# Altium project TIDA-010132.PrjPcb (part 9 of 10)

## Sheet AFE2-LMX2594.SchDoc
size 558 x 431 mm; Date: Not shown in title block; ApprovedBy: Not shown in title block; CheckedBy: Not shown in title block; Author: Not shown in title block; CompanyName: Not shown in title block; DrawnBy: Avinash N; Engineer: Not shown in title block; Organization: Not shown in title block; Address1: Not shown in title block; Address2: Not shown in title block; Address3: Not shown in title block; Address4: Not shown in title block; DocumentNumber: 1; Revision: Use project parameter SCH_Rev; SheetNumber: 15; SheetTotal: 32; PageSetup: Record=PageOptions¦CenterHorizontal=True¦CenterVertical=True¦PrintScale=1.00¦XCorrection=1.00¦YCorrection=1.00¦PrintKind=0¦BorderSize=5000000¦LeftOffset=0¦BottomOffset=0¦Orientation=2¦PaperLength=1000¦PaperWidth=1000¦Scale=100¦PaperSource=15¦PrintQuality=600¦MediaType=1¦DitherType=10¦PaperKind=Letter¦PrintScaleMode=1
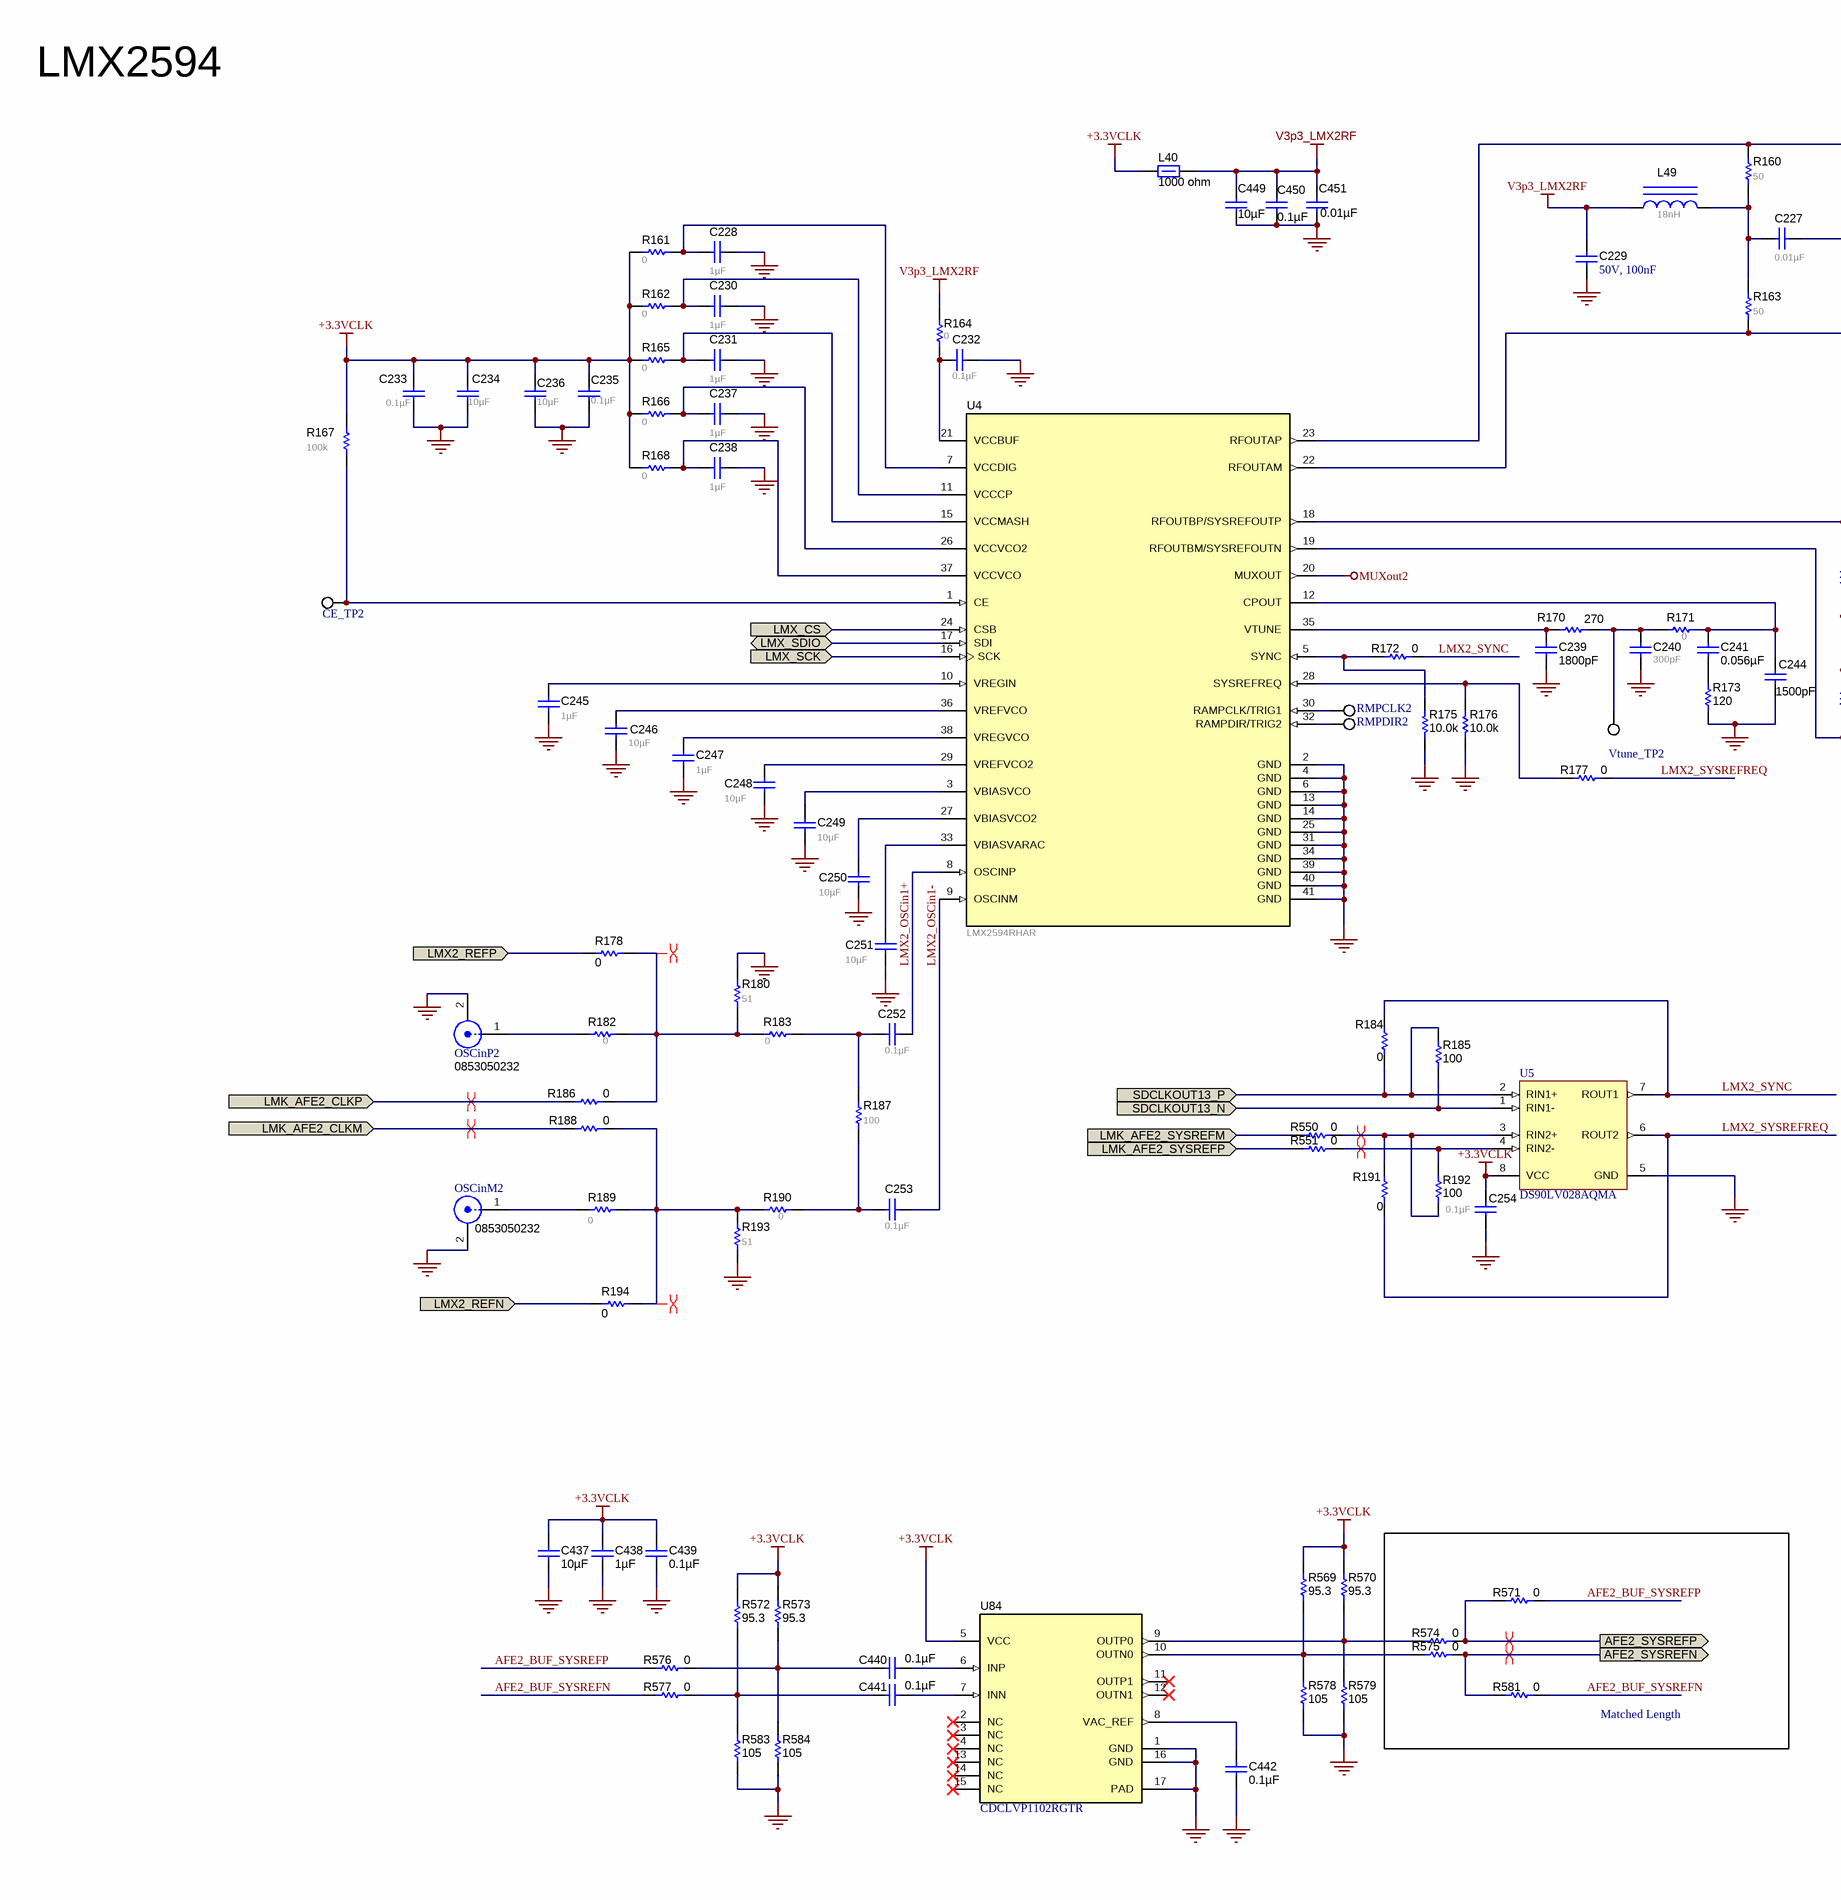
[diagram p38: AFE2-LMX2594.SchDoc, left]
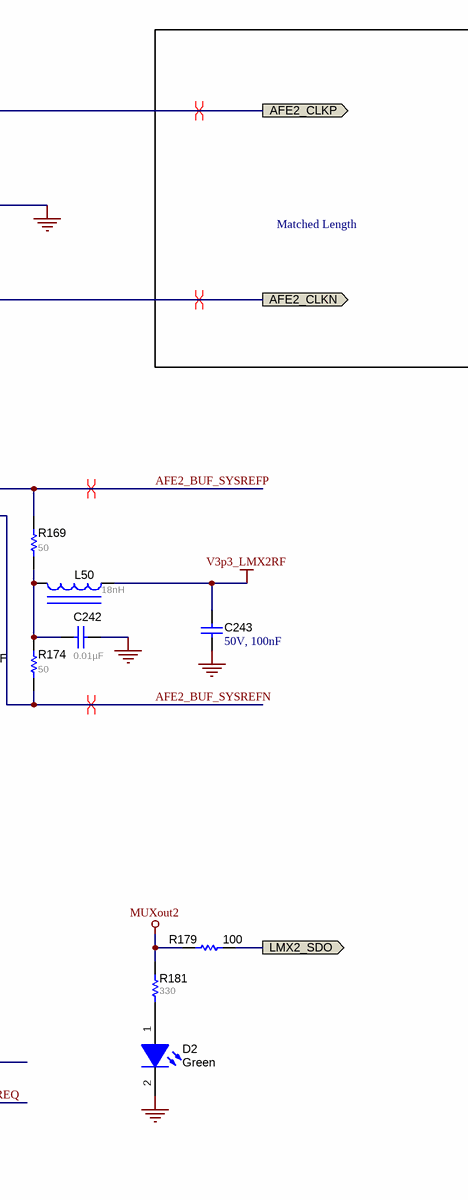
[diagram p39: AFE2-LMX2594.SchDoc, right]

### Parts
C227  ValueDisplayed: 0.01µF  [0402_065]  (hidden comment: 520L103KT16T)
C228  ValueDisplayed: 1µF  [0603]  (hidden comment: C1608X7R1C105K080AC)
C229  50V, 100nF  [0603_1.6x0.8x0.8mm_Reflow Soldering]
C230  ValueDisplayed: 1µF  [0603L]  (hidden comment: C1608X7R1C105K080AC)
C231  ValueDisplayed: 1µF  [0603L]  (hidden comment: C1608X7R1C105K080AC)
C232  ValueDisplayed: 0.1µF  [0603L]  (hidden comment: 0603YC104JAT2A)
C233  ValueDisplayed: 0.1µF  [0603]  (hidden comment: 0603YC104JAT2A)
C234  ValueDisplayed: 10µF  [0805]  (hidden comment: C0805C106K8PACTU)
C235  ValueDisplayed: 0.1µF  [0603]  (hidden comment: 0603YC104JAT2A)
C236  ValueDisplayed: 10µF  [0805]  (hidden comment: C0805C106K8PACTU)
C237  ValueDisplayed: 1µF  [0603]  (hidden comment: C1608X7R1C105K080AC)
C238  ValueDisplayed: 1µF  [0603]  (hidden comment: C1608X7R1C105K080AC)
C239  ValueDisplayed: 1800pF  [0603]  (hidden comment: GRM1885C1H182JA01D)
C240  ValueDisplayed: 300pF  [0603]  (hidden comment: GRM1885C2A301JA01D)
C241  ValueDisplayed: 0.056µF  [0603]  (hidden comment: C0603C563J4RACTU)
C242  ValueDisplayed: 0.01µF  [0402_065]  (hidden comment: 520L103KT16T)
C243  50V, 100nF  [0603_1.6x0.8x0.8mm_Reflow Soldering]
C244  ValueDisplayed: 1500pF  [0603]  (hidden comment: 06031C152JAT2A)
C245  ValueDisplayed: 1µF  [0603]  (hidden comment: C1608X7R1C105K080AC)
C246  ValueDisplayed: 10µF  [0603]  (hidden comment: C1608X5R1A106M080AC)
C247  ValueDisplayed: 1µF  [0603]  (hidden comment: C1608X7R1C105K080AC)
C248  ValueDisplayed: 10µF  [0603]  (hidden comment: C1608X5R1A106M080AC)
C249  ValueDisplayed: 10µF  [0603]  (hidden comment: C1608X5R1A106M080AC)
C250  ValueDisplayed: 10µF  [0603]  (hidden comment: C1608X5R1A106M080AC)
C251  ValueDisplayed: 10µF  [0603]  (hidden comment: C1608X5R1A106M080AC)
C252  ValueDisplayed: 0.1µF  [0603L]  (hidden comment: 0603YC104JAT2A)
C253  ValueDisplayed: 0.1µF  [0603L]  (hidden comment: 0603YC104JAT2A)
C254  ValueDisplayed: 0.1µF  [0603]  (hidden comment: 0603YC104JAT2A)
C437  ValueDisplayed: 10µF  [0603]  (hidden comment: EMK107BBJ106MA-T)
C438  ValueDisplayed: 1µF  [0402]  (hidden comment: C1005X7S1A105K050BC)
C439  ValueDisplayed: 0.1µF  [0402]  (hidden comment: GRM155R71C104KA88D)
C440  ValueDisplayed: 0.1µF  [0402]  (hidden comment: C1005X7R1E104M050BB)
C441  ValueDisplayed: 0.1µF  [0402]  (hidden comment: C1005X7R1E104M050BB)
C442  ValueDisplayed: 0.1µF  [0402]  (hidden comment: GRM155R71C104KA88D)
C449  ValueDisplayed: 10µF  [1206_190]  (hidden comment: C3216X7R1E106M160AE)
C450  ValueDisplayed: 0.1µF  [0603]  (hidden comment: CGA3E2X7R1H104K080AA)
C451  ValueDisplayed: 0.01µF  [0603]  (hidden comment: GCM188R71H103KA37D)
CE_TP2  5002  [Keystone5002]  (value not drawn)
D2  value Green  [LTST-C191_Green]  (hidden comment: LTST-C191TGKT)
L40  ValueDisplayed: 1000 ohm  [1806_HighSpeed]  (hidden comment: BLM41PG102SN1L)
L49  ValueDisplayed: 18nH  [IND_LQG15H]  (hidden comment: LQG15HS18NJ02D)
L50  ValueDisplayed: 18nH  [IND_LQG15H]  (hidden comment: LQG15HS18NJ02D)
OSCinM2  0853050232  [Molex_0853050232]
OSCinP2  0853050232  [Molex_0853050232]
R160  ValueDisplayed: 50  [0402L]  (hidden comment: FC0402E50R0BST1)
R161  value 0  [0603]  (hidden comment: CRCW06030000Z0EA)
R162  value 0  [0603L]  (hidden comment: CRCW06030000Z0EA)
R163  ValueDisplayed: 50  [0402L]  (hidden comment: FC0402E50R0BST1)
R164  value 0  [0603L]  (hidden comment: CRCW06030000Z0EA)
R165  value 0  [0603L]  (hidden comment: CRCW06030000Z0EA)
R166  value 0  [0603]  (hidden comment: CRCW06030000Z0EA)
R167  ValueDisplayed: 100k  [0603]  (hidden comment: CRCW0603100KJNEA)
R168  value 0  [0603]  (hidden comment: CRCW06030000Z0EA)
R169  ValueDisplayed: 50  [0402L]  (hidden comment: FC0402E50R0BST1)
R170  ValueDisplayed: 270  [0603]  (hidden comment: RC0603JR-07270RL)
R171  ValueDisplayed: 0  [0603]  (hidden comment: CRCW06030000Z0EA)
R172  ValueDisplayed: 0  [0402]  (hidden comment: CRCW04020000Z0ED)
R173  ValueDisplayed: 120  [0603]  (hidden comment: RT0603DRE07120RL)
R174  ValueDisplayed: 50  [0402L]  (hidden comment: FC0402E50R0BST1)
R175  ValueDisplayed: 10.0k  [0402]  (hidden comment: CRCW040210K0DHEDP)
R176  ValueDisplayed: 10.0k  [0402]  (hidden comment: CRCW040210K0DHEDP)
R177  ValueDisplayed: 0  [0402]  (hidden comment: CRCW04020000Z0ED)
R178  ValueDisplayed: 0  [0402]  (hidden comment: CRCW04020000Z0ED)
R179  ValueDisplayed: 100  [0603]  (hidden comment: CRCW0603100RFKEA)
R180  ValueDisplayed: 51  [0603]  (hidden comment: CRCW060351R0JNEA)
R181  value 330  [0603]  (hidden comment: RC0603JR-07330RL)
R182  ValueDisplayed: 0  [0603]  (hidden comment: CRCW06030000Z0EA)
R183  ValueDisplayed: 0  [0603]  (hidden comment: CRCW06030000Z0EA)
R184  ValueDisplayed: 0  [0402]  (hidden comment: CRCW04020000Z0ED)
R185  ValueDisplayed: 100  [0402]  (hidden comment: CRCW0402100RJNED)
R186  ValueDisplayed: 0  [0402]  (hidden comment: CRCW04020000Z0ED)
R187  ValueDisplayed: 100  [0603L]  (hidden comment: CRCW0603100RFKEA)
R188  ValueDisplayed: 0  [0402]  (hidden comment: CRCW04020000Z0ED)
R189  ValueDisplayed: 0  [0603]  (hidden comment: CRCW06030000Z0EA)
R190  ValueDisplayed: 0  [0603]  (hidden comment: CRCW06030000Z0EA)
R191  ValueDisplayed: 0  [0402]  (hidden comment: CRCW04020000Z0ED)
R192  ValueDisplayed: 100  [0402]  (hidden comment: CRCW0402100RJNED)
R193  ValueDisplayed: 51  [0603]  (hidden comment: CRCW060351R0JNEA)
R194  ValueDisplayed: 0  [0402]  (hidden comment: CRCW04020000Z0ED)
R550  ValueDisplayed: 0  [0402]  (hidden comment: CRCW04020000Z0ED)
R551  ValueDisplayed: 0  [0402]  (hidden comment: CRCW04020000Z0ED)
R569  ValueDisplayed: 95.3  [0402]  (hidden comment: CRCW040295R3FKED)
R570  ValueDisplayed: 95.3  [0402]  (hidden comment: CRCW040295R3FKED)
R571  ValueDisplayed: 0  [0402]  (hidden comment: CRCW04020000Z0ED)
R572  ValueDisplayed: 95.3  [0402]  (hidden comment: CRCW040295R3FKED)
R573  ValueDisplayed: 95.3  [0402]  (hidden comment: CRCW040295R3FKED)
R574  ValueDisplayed: 0  [0402]  (hidden comment: CRCW04020000Z0ED)
R575  ValueDisplayed: 0  [0402]  (hidden comment: CRCW04020000Z0ED)
R576  ValueDisplayed: 0  [0402]  (hidden comment: CRCW04020000Z0ED)
R577  ValueDisplayed: 0  [0402]  (hidden comment: CRCW04020000Z0ED)
R578  ValueDisplayed: 105  [0402]  (hidden comment: CRCW0402105RFKED)
R579  ValueDisplayed: 105  [0402]  (hidden comment: CRCW0402105RFKED)
R581  ValueDisplayed: 0  [0402]  (hidden comment: CRCW04020000Z0ED)
R583  ValueDisplayed: 105  [0402]  (hidden comment: CRCW0402105RFKED)
R584  ValueDisplayed: 105  [0402]  (hidden comment: CRCW0402105RFKED)
RMPCLK2  5002  [Keystone5002]  (value not drawn)
RMPDIR2  5002  [Keystone5002]  (value not drawn)
U4  LMX2594RHAR  [RHA0040A]
U5  DS90LV028AQMA  [M08A_N]
U84  CDCLVP1102RGTR  [RGT0016B]
Vtune_TP2  5002  [Keystone5002]  (value not drawn)

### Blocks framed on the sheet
Matched Length: R571 R574 R575 R581

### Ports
AFE2_CLKN (out), AFE2_CLKP (out), AFE2_SYSREFN (out), AFE2_SYSREFP (out), LMK_AFE2_CLKM (in), LMK_AFE2_CLKP (in), LMK_AFE2_SYSREFM (in), LMK_AFE2_SYSREFP (in), LMX2_REFN (in), LMX2_REFP (in), LMX2_SDO (out), LMX_CS (in), LMX_SCK (in), LMX_SDIO (bidir), SDCLKOUT13_N (in), SDCLKOUT13_P (in)

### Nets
+3.3VCLK: C233.2 C234.2 C235.2 C236.2 C254.2 C437.1 C438.1 C439.1 L40.1 R161.1 R162.1 R165.1 R166.2 R167.1 R168.2 R569.2 R570.2 R572.2 R573.2 U5.8(VCC) U84.5(VCC)
GND: C227.1 C228.1 C229.2 C230.1 C231.2 C232.1 C233.1 C234.1 C235.1 C236.1 C237.1 C238.1 C239.1 C240.2 C242.1 C243.2 C244.2 C245.1 C246.2 C247.1 C248.2 C249.2 C250.1 C251.1 C254.1 C437.2 C438.2 C439.2 C442.2 C449.1 C450.2 C451.2 D2.2(K) OSCinM2.2 OSCinP2.2 R173.2 R175.2 R176.2 R180.2 R193.1 R578.1 R579.1 R583.1 R584.1 U4.2(GND) U4.4(GND) U4.6(GND) U4.13(GND) U4.14(GND) U4.25(GND) U4.31(GND) U4.34(GND) U4.39(GND) U4.40(GND) U4.41(GND) U5.5(GND) U84.1(GND) U84.16(GND) U84.17(PAD)
MUXout2: R179.1 R181.2 U4.20(MUXOUT)
V3p3_LMX2RF: C229.1 C243.1 C449.2 C450.1 C451.1 L40.2 L49.1 L50.1 R164.1
AFE2_BUF_SYSREFN: R174.1 R577.1 R581.2 U4.19(RFOUTBM/SYSREFOUTN)
AFE2_BUF_SYSREFP: R169.2 R571.2 R576.1 U4.18(RFOUTBP/SYSREFOUTP)
AFE2_CLKN: R163.1 U4.22(RFOUTAM) ; port AFE2_CLKN
AFE2_CLKP: R160.1 U4.23(RFOUTAP) ; port AFE2_CLKP
AFE2_SYSREFN: R575.2 R581.1 ; port AFE2_SYSREFN
AFE2_SYSREFP: R571.1 R574.2 ; port AFE2_SYSREFP
LMK_AFE2_CLKM: R188.1 ; port LMK_AFE2_CLKM
LMK_AFE2_CLKP: R186.1 ; port LMK_AFE2_CLKP
LMK_AFE2_SYSREFM: R550.1 ; port LMK_AFE2_SYSREFM
LMK_AFE2_SYSREFP: R551.1 ; port LMK_AFE2_SYSREFP
LMX2_OSCin1+: C252.2 U4.8(OSCINP)
LMX2_OSCin1-: C253.2 U4.9(OSCINM)
LMX2_REFN: R194.1 ; port LMX2_REFN
LMX2_REFP: R178.2 ; port LMX2_REFP
LMX2_SDO: R179.2 ; port LMX2_SDO
LMX2_SYNC: R172.2 R184.1 U5.7(ROUT1)
LMX2_SYSREFREQ: R177.2 R191.2 U5.6(ROUT2)
LMX_CS: U4.24(CSB) ; port LMX_CS
LMX_SCK: U4.16(SCK) ; port LMX_SCK
LMX_SDIO: U4.17(SDI) ; port LMX_SDIO
SDCLKout13_N: R185.1 U5.1(RIN1-) ; port SDCLKOUT13_N
SDCLKout13_P: R184.2 R185.2 U5.2(RIN1+) ; port SDCLKOUT13_P
NetC227_2: C227.2 L49.2 R160.2 R163.2
NetC228_2: C228.2 R161.2 U4.7(VCCDIG)
NetC230_2: C230.2 R162.2 U4.11(VCCCP)
NetC231_1: C231.1 R165.2 U4.15(VCCMASH)
NetC232_2: C232.2 R164.2 U4.21(VCCBUF)
NetC237_2: C237.2 R166.1 U4.26(VCCVCO2)
NetC238_2: C238.2 R168.1 U4.37(VCCVCO)
NetC239_2: C239.2 R170.1 U4.35(VTUNE)
NetC240_1: C240.1 R170.2 R171.2 Vtune_TP2.1
NetC241_1: C241.1 C244.1 R171.1 U4.12(CPOUT)
NetC241_2: C241.2 R173.1
NetC242_2: C242.2 L50.2 R169.1 R174.2
NetC245_2: C245.2 U4.10(VREGIN)
NetC246_1: C246.1 U4.36(VREFVCO)
NetC247_2: C247.2 U4.38(VREGVCO)
NetC248_1: C248.1 U4.29(VREFVCO2)
NetC249_1: C249.1 U4.3(VBIASVCO)
NetC250_2: C250.2 U4.27(VBIASVCO2)
NetC251_2: C251.2 U4.33(VBIASVARAC)
NetC252_1: C252.1 R183.2 R187.2
NetC253_1: C253.1 R187.1 R190.1
NetC440_1: C440.1 R573.1 R576.2 R584.2
NetC440_2: C440.2 U84.6(INP)
NetC441_1: C441.1 R572.1 R577.2 R583.2
NetC441_2: C441.2 U84.7(INN)
NetC442_1: C442.1 U84.8(VAC_REF)
NetCE_TP2_1: CE_TP2.1 R167.2 U4.1(CE)
NetD2_1: D2.1(A) R181.1
NetOSCinM2_1: OSCinM2.1 R189.1
NetOSCinP2_1: OSCinP2.1 R182.1
NetR172_1: R172.1 R175.1 U4.5(SYNC)
NetR176_1: R176.1 R177.1 U4.28(SYSREFREQ)
NetR178_1: R178.1 R180.1 R182.2 R183.1 R186.2
NetR188_2: R188.2 R189.2 R190.2 R193.2 R194.2
NetR191_1: R191.1 R192.1 R550.2 U5.3(RIN2+)
NetR192_2: R192.2 R551.2 U5.4(RIN2-)
NetR569_1: R569.1 R575.1 R578.2 U84.10(OUTN0)
NetR570_1: R570.1 R574.1 R579.2 U84.9(OUTP0)
NetRMPCLK2_1: RMPCLK2.1 U4.30(RAMPCLK/TRIG1)
NetRMPDIR2_1: RMPDIR2.1 U4.32(RAMPDIR/TRIG2)

Not connected (* = marked no-connect by the designer): U84 2(NC)* 3(NC)* 4(NC)* 11(OUTP1)* 12(OUTN1)* 13(NC)* 14(NC)* 15(NC)*

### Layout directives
differential pair: AFE2_BUF_SYSREFN, AFE2_BUF_SYSREFP, AFE2_CLKN, AFE2_CLKP, AFE2_SYSREFN, AFE2_SYSREFP, LMK_AFE2_CLKM, LMK_AFE2_CLKP, NetR178_1, NetR188_2, NetR191_1, NetR192_2

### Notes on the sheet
- LMX2594
- Matched Length

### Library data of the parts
C227 C242 = 520L103KT16T: CAP, CERM, 0.01 µF, 16 V, +/- 10%, X7R, 0402; Manufacturer: AT Ceramics; Polarized: N; CompType: Capacitor; Value: 0.01uF; U/M: EA; Cap_F: 0.00000001; Tolerance_%: 10; Value1: Unknown; VDC_V: 16; Value2: 16V; TaMin_C: -55; TaMax_C: 125; Cap_Case: 0402; AEC Category: Q200; SizeArea_mm2: 0.5; SizeAreaWB_mm2: 3; SizeX_mm: 1; SizeZ_mm: 0.65
C228 C237 C238 = C1608X7R1C105K080AC: CAP, CERM, 1 µF, 16 V, +/- 10%, X7R, 0603; Manufacturer: TDK; ESR_ohm: 0.0057; Polarized: N; TaMax_C: 125; TaMin_C: -55; Tolerance_%: 10; VDC_V: 16; Cap_F: 0.000001; CompType: Capacitor; Value: 1uF; Value1: 0.0057 ohm; Value2: 16V; U/M: EA; SizeArea_mm2: 1.28; SizeAreaWB_mm2: 4.68; SizeX_mm: 1.6; SizeY_mm: 0.8; SizeZ_mm: 1; AEC Category: Q200
C229 C243 = 885012206095: WCAP-CSGP Ceramic Capacitors, 0603, X7R, 50V, 100nF; Manufacturer: Wurth Electronics Inc.; Rated Voltage: 50V DC
C230 C231 = C1608X7R1C105K080AC: CAP, CERM, 1 µF, 16 V, +/- 10%, X7R, 0603; Manufacturer: TDK; Cap_Case: 0603; ESR_ohm: 0.0057; Polarized: N; TaMax_C: 125; TaMin_C: -55; Tolerance_%: 10; VDC_V: 16; Cap_F: 0.000001; CompType: Capacitor; Value: 1uF; Value1: 0.0057 ohm; Value2: 16V; U/M: EA; SizeArea_mm2: 1.28; SizeAreaWB_mm2: 4.68; SizeX_mm: 1.6; SizeY_mm: 0.8; SizeZ_mm: 1; AEC Category: Q200
C232 C252 C253 = 0603YC104JAT2A: CAP, CERM, 0.1uF, 16V, +/-5%, X7R, 0603; Manufacturer: AVX; Cap_Case: 0603; ESR_Ohm: 0.039; Polarized: N; TaMax_C: 125; TaMin_C: -55; Tolerance_%: 5; VDC_V: 16; Cap_F: 0.0000001; CompType: Capacitor; Value1: 0.039 ohm; U/M: EA
C233 C235 C254 = 0603YC104JAT2A: CAP, CERM, 0.1uF, 16V, +/-5%, X7R, 0603; Manufacturer: AVX; ESR_Ohm: 0.039; Polarized: N; TaMax_C: 125; TaMin_C: -55; Tolerance_%: 5; VDC_V: 16; Cap_F: 0.0000001; CompType: Capacitor; Value1: 0.039 ohm; U/M: EA
C234 C236 = C0805C106K8PACTU: CAP, CERM, 10uF, 10V, +/-10%, X5R, 0805; Manufacturer: Kemet; ESR_Ohm: 0.003; IRMS_A: 11.43; Polarized: N; TaMax_C: 85; TaMin_C: -55; Tolerance_%: 10; Cap_F: 0.00001; CompType: Capacitor; U/M: EA; Value1: 0.003 ohm
C239 = GRM1885C1H182JA01D: CAP, CERM, 1800 pF, 50 V, +/- 5%, C0G/NP0, 0603; Manufacturer: MuRata; Polarized: N; TaMax_C: 125; TaMin_C: -55; Tolerance_%: 5; VDC_V: 50; Cap_F: 0.0000000018; CompType: Capacitor; Value: 1800pF; Value1: Unknown; Value2: 50V; U/M: EA; SizeArea_mm2: 1.28; SizeAreaWB_mm2: 4.68; SizeX_mm: 1.6; SizeY_mm: 0.8; SizeZ_mm: 1; AEC Category: Q200
C240 = GRM1885C2A301JA01D: CAP, CERM, 300pF, 100V, +/-5%, C0G/NP0, 0603; Manufacturer: MuRata; Polarized: N; TaMax_C: 125; TaMin_C: -55; Tolerance_%: 5; VDC_V: 100; Cap_F: 0.0000000003; CompType: Capacitor; Value1: Unknown; U/M: EA
C241 = C0603C563J4RACTU: CAP, CERM, 0.056 µF, 16 V, +/- 5%, X7R, 0603; Manufacturer: Kemet; Polarized: N; TaMax_C: 125; TaMin_C: -55; Tolerance_%: 5; VDC_V: 16; Cap_F: 0.000000056; CompType: Capacitor; Value: 0.056uF; Value1: Unknown; Value2: 16V; U/M: EA; AEC Category: Q200; SizeArea_mm2: 1.28; SizeAreaWB_mm2: 4.68; SizeX_mm: 1.6; SizeY_mm: 0.8; SizeZ_mm: 1
C244 = 06031C152JAT2A: CAP, CERM, 1500 pF, 100 V, +/- 5%, X7R, 0603; Manufacturer: AVX; ESR_ohm: 0.229; Polarized: N; TaMax_C: 125; TaMin_C: -55; Tolerance_%: 5; VDC_V: 100; Cap_F: 0.0000000015; CompType: Capacitor; Value: 1500pF; Value1: 0.229 ohm; Value2: 100V; U/M: EA; AEC Category: Q200; SizeArea_mm2: 1.28; SizeAreaWB_mm2: 4.68; SizeX_mm: 1.6; SizeY_mm: 0.8; SizeZ_mm: 1
C245 = C1608X7R1C105K080AC: CAP, CERM, 1 µF, 16 V, +/- 10%, X7R, 0603; Manufacturer: TDK; Polarized: N; CompType: Capacitor; Value: 1uF; U/M: EA; Cap_F: 0.000001; Tolerance_%: 10; ESR_ohm: 0.0057; Value1: 0.0057 ohm; VDC_V: 16; Value2: 16V; TaMin_C: -55; TaMax_C: 125; AEC Category: Q200
C246 C248-C251 = C1608X5R1A106M080AC: CAP, CERM, 10 µF, 10 V, +/- 20%, X5R, 0603; Manufacturer: TDK; ESR_ohm: 0.0078; IRMS_A: 1.85; Polarized: N; TaMax_C: 85; TaMin_C: -55; Tolerance_%: 20; VDC_V: 10; Cap_F: 0.00001; CompType: Capacitor; Value: 10uF; U/M: EA; Value1: 0.0078 ohm; Value2: 10V; AEC Category: Q200
C247 = C1608X7R1C105K080AC: CAP, CERM, 1 µF, 16 V, +/- 10%, X7R, 0603; Manufacturer: TDK; ESR_ohm: 0.0057; Polarized: N; TaMax_C: 125; TaMin_C: -55; Tolerance_%: 10; VDC_V: 16; Cap_F: 0.000001; CompType: Capacitor; Value: 1uF; U/M: EA; Value1: 0.0057 ohm; Value2: 16V; AEC Category: Q200
C437 = EMK107BBJ106MA-T: CAP, CERM, 10 µF, 16 V, +/- 20%, X5R, 0603; Manufacturer: Taiyo Yuden; Polarized: N; CompType: Capacitor; Value: 10uF; U/M: EA; Cap_F: 0.00001; Tolerance_%: 20; Value1: Unknown; VDC_V: 16; Value2: 16V; TaMin_C: -55; TaMax_C: 85; SizeArea_mm2: 1.28; SizeAreaWB_mm2: 4.68; SizeX_mm: 1.6; SizeY_mm: 0.8; SizeZ_mm: 1; AEC Category: Q200
C438 = C1005X7S1A105K050BC: CAP, CERM, 1 µF, 10 V, +/- 10%, X7S, 0402; Manufacturer: TDK; Polarized: N; CompType: Capacitor; Value: 1uF; U/M: EA; Cap_F: 0.000001; Tolerance_%: 10; ESR_ohm: 0.011416; Value1: 0.011416 ohm; Value2: 10V; IRMS_A: 1.483; TaMin_C: -55; TaMax_C: 125; SizeArea_mm2: 0.5; SizeAreaWB_mm2: 3; SizeX_mm: 1; SizeZ_mm: 0.6; AEC Category: Q200
C439 C442 = GRM155R71C104KA88D: CAP, CERM, 0.1 µF, 16 V, +/- 10%, X7R, 0402; Manufacturer: MuRata; Polarized: N; CompType: Capacitor; Value: 0.1uF; U/M: EA; Cap_F: 0.0000001; Tolerance_%: 10; Value1: Unknown; VDC_V: 16; Value2: 16V; TaMin_C: -55; TaMax_C: 125; SizeArea_mm2: 0.5; SizeAreaWB_mm2: 3; SizeX_mm: 1; SizeZ_mm: 0.6; AEC Category: Q200
C440 C441 = C1005X7R1E104M050BB: CAP, CERM, 0.1 µF, 25 V, +/- 20%, X7R, 0402; Manufacturer: TDK; Polarized: N; TaMax_C: 125; TaMin_C: -55; Tolerance_%: 20; VDC_V: 25; Cap_F: 0.0000001; CompType: Capacitor; Value: 0.1uF; Value1: Unknown; Value2: 25V; U/M: EA; SizeArea_mm2: 0.5; SizeAreaWB_mm2: 3; SizeX_mm: 1; SizeZ_mm: 0.6; AEC Category: Q200
C449 = C3216X7R1E106M160AE: CAP, CERM, 10 µF, 25 V, +/- 20%, X7R, 1206_190; Manufacturer: TDK; Polarized: N; CompType: Capacitor; Value: 10uF; U/M: EA; Cap_F: 0.00001; Tolerance_%: 20; Value1: Unknown; VDC_V: 25; Value2: 25V; TaMin_C: -55; TaMax_C: 125; Cap_Case: 1206; SizeArea_mm2: 5.12; SizeAreaWB_mm2: 10.92; SizeX_mm: 3.2; SizeY_mm: 1.6; SizeZ_mm: 1.9; AEC Category: Q200
C450 = CGA3E2X7R1H104K080AA: CAP, CERM, 0.1 µF, 50 V, +/- 10%, X7R, AEC-Q200 Grade 1, 0603; Manufacturer: TDK; Polarized: N; CompType: Capacitor; Value: 0.1uF; U/M: EA; Cap_F: 0.0000001; Tolerance_%: 10; ESR_ohm: 0.0296; Value1: 0.0296 ohm; VDC_V: 50; Value2: 50V; IRMS_A: 0.97199; TaMin_C: -55; TaMax_C: 125; SizeArea_mm2: 1.28; SizeAreaWB_mm2: 4.68; SizeX_mm: 1.6; SizeY_mm: 0.8; SizeZ_mm: 1; AEC Category: Q200; AEC Qualified: Y
C451 = GCM188R71H103KA37D: CAP, CERM, 0.01 µF, 50 V, +/- 10%, X7R, AEC-Q200 Grade 1, 0603; Manufacturer: MuRata; Polarized: N; CompType: Capacitor; Value: 0.01uF; U/M: EA; Cap_F: 0.00000001; Tolerance_%: 10; Value1: Unknown; VDC_V: 50; Value2: 50V; TaMin_C: -55; TaMax_C: 125; SizeArea_mm2: 1.28; SizeAreaWB_mm2: 4.68; SizeX_mm: 1.6; SizeY_mm: 0.8; SizeZ_mm: 1; AEC Category: Q200; AEC Qualified: Y
CE_TP2 RMPCLK2 RMPDIR2 Vtune_TP2 = 5002: Test Point, Miniature, White, TH; Manufacturer: Keystone; CompType: Test Point Loop; ContactFinish: Silver; Green_Lifecycle: Active; Green_REACh: Passed
D2 = LTST-C191TGKT: LED, Green, SMD; Manufacturer: Lite-On; Type: InGaN; Vf_V: 3.2; Value2: 3.2V; Io_A: 0.02; Value1: W; U/M: EA
L40 = BLM41PG102SN1L: Ferrite Bead, 1000 ohm @ 100 MHz, 1.5 A, 1806; Manufacturer: MuRata; Imax_A: 1.5; DCR_ohm: 0.09; Value1: 0.09 ohm; Value2: 1.5A; SizeAreaWB_mm2: 14.3; SizeArea_mm2: 7.2; SizeX_mm: 4.5; SizeY_mm: 1.6; SizeZ_mm: 1.85; ZTyp@100MHz_Ohm: 1000
L49 L50 = LQG15HS18NJ02D: Inductor, Multilayer, Air Core, 18 nH, 0.3 A, 0.36 ohm, SMD; Manufacturer: MuRata; Value: 18nH; Ind_H: 18.0E-9; Imax_A: 0.3; Irms: 0.3A @ C rise; Isat: 0.3A @ % inductance drop; DCR_ohm: 0.36; Value2: 0.3A; AEC Category: Q200
OSCinM2 OSCinP2 = CMP-0077224-1: Plug, 50 Ohm, Straight, SMT; Manufacturer: Molex; Cert_UL: Y; ContactFinish: Gold; CT: False; Gender: Male; Voltage_V: 335V
R160 R163 R169 R174 = FC0402E50R0BST1: RES, 50, 0.1%, 0.05 W, 0402; Manufacturer: Vishay-Dale; CompType: Resistor; Value: 50; Value_Code: 50R0; Tolerance_%: 0.1; Power_W: 0.05; Value2: 0.05W; TempCo: 25 ppm/C; U/M: EA; SizeArea_mm2: 0.5; SizeX_mm: 1; SizeZ_mm: 0.6; AEC Category: Q200; AEC Qualified: N
R161 R162 R164-R166 R168 = CRCW06030000Z0EA: RES, 0 ohm, 5%, 0.1W, 0603; Manufacturer: Vishay-Dale; CompType: Resistor; Tolerance_%: 5; VDC_V: 75; Power_W: 0.1; U/M: EA; Value_Code: 0000; EIA_Code: E24
R167 = CRCW0603100KJNEA: RES, 100 k, 5%, 0.1 W, 0603; Manufacturer: Vishay-Dale; CompType: Resistor; Tolerance_%: 5; VDC_V: 75; Power_W: 0.1; Res_ohm: 100000; Value: 100k; U/M: EA; Value2: 0.1W; EIA_Code: E24; TempCo: 200 ppm/C; SizeArea_mm2: 1.28; SizeX_mm: 1.6; SizeY_mm: 0.8; SizeZ_mm: 1; AEC Category: Q200
R170 = RC0603JR-07270RL: RES, 270, 5%, 0.1 W, 0603; Manufacturer: Yageo America; CompType: Resistor; Tolerance_%: 5; VDC_V: 50; Power_W: 0.1; Value: 270; U/M: EA; Value_Code: 270R; Value2: 0.1W; EIA_Code: E24; TempCo: 100 ppm/C; SizeArea_mm2: 1.28; SizeX_mm: 1.6; SizeY_mm: 0.8; SizeZ_mm: 1; AEC Category: Q200
R171 R182 R183 R189 R190 = CRCW06030000Z0EA: RES, 0, 5%, 0.1 W, 0603; Manufacturer: Vishay-Dale; CompType: Resistor; Tolerance_%: 5; VDC_V: 75; Power_W: 0.1; Value: 0; U/M: EA; Value_Code: 0000; Value2: 0.1W; EIA_Code: E24; TempCo: 200 ppm/C; SizeArea_mm2: 1.28; SizeX_mm: 1.6; SizeY_mm: 0.8; SizeZ_mm: 1; AEC Category: Q200
R172 R177 R184 R186 R188 R191 R550 R551 R571 R574-R577 R581 = CRCW04020000Z0ED: RES, 0, 5%, 0.063 W, 0402; Manufacturer: Vishay-Dale; CompType: Resistor; Value: 0; Value_Code: 0000; Tolerance_%: 5; Power_W: 0.063; Value2: 0.063W; VDC_V: 50; TempCo: 200 ppm/C; SizeArea_mm2: 0.5; SizeX_mm: 1; SizeZ_mm: 0.6; EIA_Code: E24; U/M: EA; AEC Category: Q200
R173 = RT0603DRE07120RL: RES, 120, 0.5%, 0.1 W, 0603; Manufacturer: Yageo America; CompType: Resistor; Tolerance_%: 0.5; VDC_V: 75; Power_W: 0.1; Value: 120; U/M: EA; Value_Code: 120R; Value2: 0.1W; TempCo: 50 ppm/C; EIA_Code: E192; SizeArea_mm2: 1.28; SizeX_mm: 1.6; SizeY_mm: 0.8; SizeZ_mm: 1; AEC Category: Q200
R175 R176 = CRCW040210K0DHEDP: RES, 10.0 k, 0.5%, 0.063 W, 0402; Manufacturer: Vishay-Dale; CompType: Resistor; Value: 10.0k; Res_ohm: 10000; Value_Code: 10k0; Tolerance_%: 0.5; Power_W: 0.063; Value2: 0.063W; VDC_V: 50; TempCo: 50 ppm/C; SizeX_mm: 1; SizeZ_mm: 0.6; EIA_Code: E192; U/M: EA; AEC Category: Q200
R178 R194 = CRCW04020000Z0ED: RES, 0, 5%, 0.063 W, 0402; Manufacturer: Vishay-Dale; CompType: Resistor; Tolerance_%: 5; VDC_V: 50; Power_W: 0.063; Value: 0; U/M: EA; Value_Code: 0000; Value2: 0.063W; EIA_Code: E24; TempCo: 200 ppm/C; SizeArea_mm2: 0.5; SizeX_mm: 1; SizeZ_mm: 0.6; AEC Category: Q200
R179 = CRCW0603100RFKEA: RES, 100, 1%, 0.1 W, 0603; Manufacturer: Vishay-Dale; CompType: Resistor; Value: 100; Value_Code: 100R; Tolerance_%: 1; Power_W: 0.1; Value2: 0.1W; VDC_V: 75; TempCo: 100 ppm/C; SizeArea_mm2: 1.28; SizeX_mm: 1.6; SizeY_mm: 0.8; EIA_Code: E96; U/M: EA; AEC Category: Q200
R180 R193 = CRCW060351R0JNEA: RES, 51, 5%, 0.1 W, 0603; Manufacturer: Vishay-Dale; CompType: Resistor; Value: 51; Value_Code: 51R0; Tolerance_%: 5; Power_W: 0.1; Value2: 0.1W; VDC_V: 75; TempCo: 200 ppm/C; EIA_Code: E24; U/M: EA; SizeArea_mm2: 1.28; SizeX_mm: 1.6; SizeY_mm: 0.8; SizeZ_mm: 1; AEC Category: Q200
R181 = RC0603JR-07330RL: RES, 330 ohm, 5%, 0.1W, 0603; Manufacturer: Yageo America; CompType: Resistor; Tolerance_%: 5; VDC_V: 50; Power_W: 0.1; U/M: EA; Value_Code: 330R; EIA_Code: E24
R185 R192 = CRCW0402100RJNED: RES, 100, 5%, 0.063 W, 0402; Manufacturer: Vishay-Dale; CompType: Resistor; Value: 100; Value_Code: 100R; Tolerance_%: 5; Power_W: 0.063; Value2: 0.063W; VDC_V: 50; TempCo: 200 ppm/C; SizeArea_mm2: 0.5; SizeX_mm: 1; SizeZ_mm: 0.6; EIA_Code: E24; U/M: EA; AEC Category: Q200
R187 = CRCW0603100RFKEA: RES, 100, 1%, 0.1 W, 0603; Manufacturer: Vishay-Dale; CompType: Resistor; Tolerance_%: 1; VDC_V: 75; Power_W: 0.1; Value: 100; U/M: EA; Value_Code: 100R; Value2: 0.1W; EIA_Code: E96; TempCo: 100 ppm/C; SizeArea_mm2: 1.28; SizeX_mm: 1.6; SizeY_mm: 0.8; AEC Category: Q200
R569 R570 R572 R573 = CRCW040295R3FKED: RES, 95.3, 1%, 0.063 W, 0402; Manufacturer: Vishay-Dale; CompType: Resistor; Value: 95.3; Value_Code: 95R3; Tolerance_%: 1; Power_W: 0.063; Value2: 0.063W; VDC_V: 50; TempCo: 100 ppm/C; SizeArea_mm2: 0.5; SizeZ_mm: 0.6; EIA_Code: E96; U/M: EA; AEC Category: Q200
R578 R579 R583 R584 = CRCW0402105RFKED: RES, 105, 1%, 0.063 W, 0402; Manufacturer: Vishay-Dale; CompType: Resistor; Value: 105; Value_Code: 105R; Tolerance_%: 1; Power_W: 0.063; Value2: 0.063W; VDC_V: 50; TempCo: 100 ppm/C; SizeArea_mm2: 0.5; SizeZ_mm: 0.6; EIA_Code: E96; U/M: EA; AEC Category: Q200
U4 = LMX2594RHAR: High Performance, Wideband PLLatinum RF Synthesizer, RHA0040A (VQFN-40); Alternate PartNumber: LMX2594RHAT; Manufacturer: Texas Instruments; SymbolCreator: Altium; SizeArea_mm2: 36; SizeAreaWB_mm2: 64; SizeX_mm: 6; SizeZ_mm: 1; CompType: IC; U/M: EA
U5 = DS90LV028AQMA: Automotive LVDS Dual Differential Line Receiver, 8-pin Narrow SOIC; Manufacturer: Texas Instruments; PackageTopMarking: NSZXTT*90LV0*28AQM; PowerWise: N; CompType: Interface IC
U84 = CMP-0075857-1: Low Jitter 1:2 Universal-to-LVPECL Buffer, RGT0016B (VQFN-16); Manufacturer: Texas Instruments; Alternate PartNumber: CDCLVP1102RGTT; SizeAreaWB_mm2: 16.0; SizeArea_mm2: 9.0; SizeZ_mm: 1.0; Green_REACh: Passed; SizeY_mm: 3.0; Green_Lifecycle: Active; U/M: EA; CompType: IC

## Sheet AFE2-POWER.SchDoc
size 431 x 279 mm; Date: Not shown in title block; ApprovedBy: Not shown in title block; CheckedBy: Not shown in title block; Author: Not shown in title block; CompanyName: Not shown in title block; DrawnBy: Avinash N; Engineer: Not shown in title block; Organization: Not shown in title block; Address1: Not shown in title block; Address2: Not shown in title block; Address3: Not shown in title block; Address4: Not shown in title block; DocumentNumber: 1; Revision: Use project parameter SCH_Rev; SheetNumber: 23; SheetTotal: 32; PageSetup: Record=PageOptions¦CenterHorizontal=True¦CenterVertical=True¦PrintScale=1.00¦XCorrection=1.00¦YCorrection=1.00¦PrintKind=0¦BorderSize=5000000¦LeftOffset=0¦BottomOffset=0¦Orientation=2¦PaperLength=1000¦PaperWidth=1000¦Scale=100¦PaperSource=15¦PrintQuality=600¦MediaType=1¦DitherType=10¦PaperKind=Letter¦PrintScaleMode=1
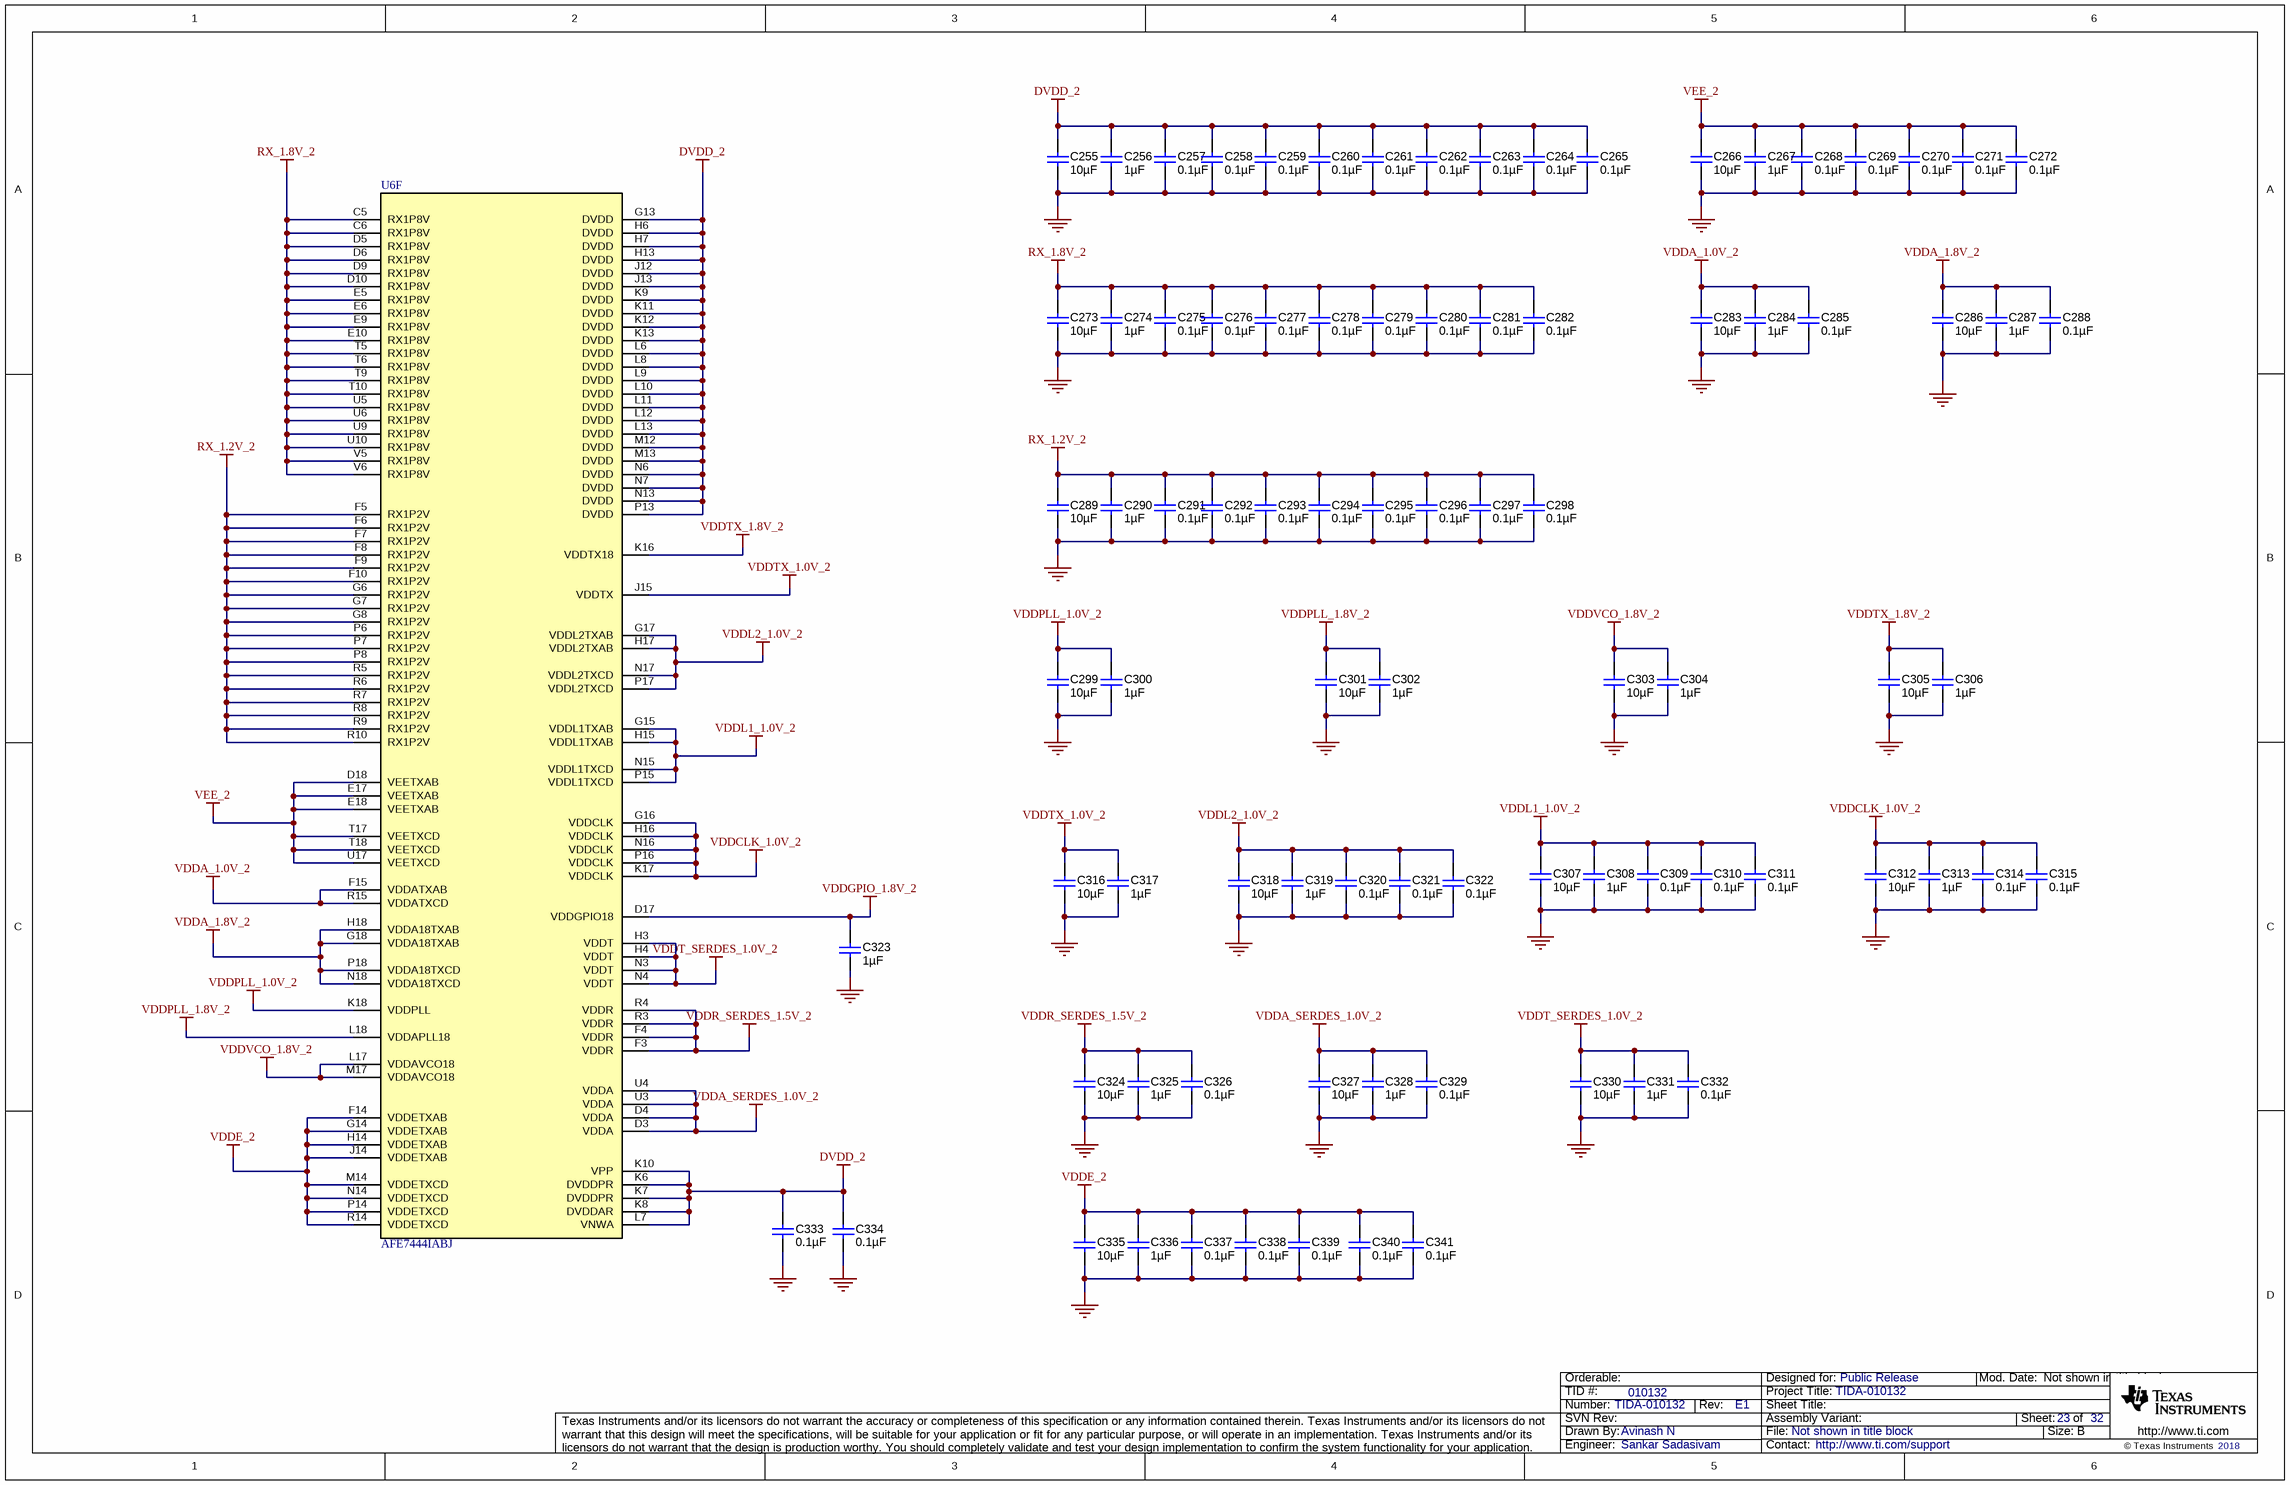
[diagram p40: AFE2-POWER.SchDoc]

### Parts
C255  ValueDisplayed: 10µF  [0402_070]  (hidden comment: GRM155R61A106ME21D)
C256  ValueDisplayed: 1µF  [0201]  (hidden comment: CL03A105MP3NSNC)
C257  ValueDisplayed: 0.1µF  [0201]  (hidden comment: GRM033C71A104KE14D)
C258  ValueDisplayed: 0.1µF  [0201]  (hidden comment: GRM033C71A104KE14D)
C259  ValueDisplayed: 0.1µF  [0201]  (hidden comment: GRM033C71A104KE14D)
C260  ValueDisplayed: 0.1µF  [0201]  (hidden comment: GRM033C71A104KE14D)
C261  ValueDisplayed: 0.1µF  [0201]  (hidden comment: GRM033C71A104KE14D)
C262  ValueDisplayed: 0.1µF  [0201]  (hidden comment: GRM033C71A104KE14D)
C263  ValueDisplayed: 0.1µF  [0201]  (hidden comment: GRM033C71A104KE14D)
C264  ValueDisplayed: 0.1µF  [0201]  (hidden comment: GRM033C71A104KE14D)
C265  ValueDisplayed: 0.1µF  [0201]  (hidden comment: GRM033C71A104KE14D)
C266  ValueDisplayed: 10µF  [0402_070]  (hidden comment: GRM155R61A106ME21D)
C267  ValueDisplayed: 1µF  [0201]  (hidden comment: CL03A105MP3NSNC)
C268  ValueDisplayed: 0.1µF  [0201]  (hidden comment: GRM033C71A104KE14D)
C269  ValueDisplayed: 0.1µF  [0201]  (hidden comment: GRM033C71A104KE14D)
C270  ValueDisplayed: 0.1µF  [0201]  (hidden comment: GRM033C71A104KE14D)
C271  ValueDisplayed: 0.1µF  [0201]  (hidden comment: GRM033C71A104KE14D)
C272  ValueDisplayed: 0.1µF  [0201]  (hidden comment: GRM033C71A104KE14D)
C273  ValueDisplayed: 10µF  [0402_070]  (hidden comment: GRM155R61A106ME21D)
C274  ValueDisplayed: 1µF  [0201]  (hidden comment: CL03A105MP3NSNC)
C275  ValueDisplayed: 0.1µF  [0201]  (hidden comment: GRM033C71A104KE14D)
C276  ValueDisplayed: 0.1µF  [0201]  (hidden comment: GRM033C71A104KE14D)
C277  ValueDisplayed: 0.1µF  [0201]  (hidden comment: GRM033C71A104KE14D)
C278  ValueDisplayed: 0.1µF  [0201]  (hidden comment: GRM033C71A104KE14D)
C279  ValueDisplayed: 0.1µF  [0201]  (hidden comment: GRM033C71A104KE14D)
C280  ValueDisplayed: 0.1µF  [0201]  (hidden comment: GRM033C71A104KE14D)
C281  ValueDisplayed: 0.1µF  [0201]  (hidden comment: GRM033C71A104KE14D)
C282  ValueDisplayed: 0.1µF  [0201]  (hidden comment: GRM033C71A104KE14D)
C283  ValueDisplayed: 10µF  [0402_070]  (hidden comment: GRM155R61A106ME21D)
C284  ValueDisplayed: 1µF  [0201]  (hidden comment: CL03A105MP3NSNC)
C285  ValueDisplayed: 0.1µF  [0201]  (hidden comment: GRM033C71A104KE14D)
C286  ValueDisplayed: 10µF  [0402_070]  (hidden comment: GRM155R61A106ME21D)
C287  ValueDisplayed: 1µF  [0201]  (hidden comment: CL03A105MP3NSNC)
C288  ValueDisplayed: 0.1µF  [0201]  (hidden comment: GRM033C71A104KE14D)
C289  ValueDisplayed: 10µF  [0402_070]  (hidden comment: GRM155R61A106ME21D)
C290  ValueDisplayed: 1µF  [0201]  (hidden comment: CL03A105MP3NSNC)
C291  ValueDisplayed: 0.1µF  [0201]  (hidden comment: GRM033C71A104KE14D)
C292  ValueDisplayed: 0.1µF  [0201]  (hidden comment: GRM033C71A104KE14D)
C293  ValueDisplayed: 0.1µF  [0201]  (hidden comment: GRM033C71A104KE14D)
C294  ValueDisplayed: 0.1µF  [0201]  (hidden comment: GRM033C71A104KE14D)
C295  ValueDisplayed: 0.1µF  [0201]  (hidden comment: GRM033C71A104KE14D)
C296  ValueDisplayed: 0.1µF  [0201]  (hidden comment: GRM033C71A104KE14D)
C297  ValueDisplayed: 0.1µF  [0201]  (hidden comment: GRM033C71A104KE14D)
C298  ValueDisplayed: 0.1µF  [0201]  (hidden comment: GRM033C71A104KE14D)
C299  ValueDisplayed: 10µF  [0402_070]  (hidden comment: GRM155R61A106ME21D)
C300  ValueDisplayed: 1µF  [0201]  (hidden comment: CL03A105MP3NSNC)
C301  ValueDisplayed: 10µF  [0402_070]  (hidden comment: GRM155R61A106ME21D)
C302  ValueDisplayed: 1µF  [0201]  (hidden comment: CL03A105MP3NSNC)
C303  ValueDisplayed: 10µF  [0402_070]  (hidden comment: GRM155R61A106ME21D)
C304  ValueDisplayed: 1µF  [0201]  (hidden comment: CL03A105MP3NSNC)
C305  ValueDisplayed: 10µF  [0402_070]  (hidden comment: GRM155R61A106ME21D)
C306  ValueDisplayed: 1µF  [0201]  (hidden comment: CL03A105MP3NSNC)
C307  ValueDisplayed: 10µF  [0402_070]  (hidden comment: GRM155R61A106ME21D)
C308  ValueDisplayed: 1µF  [0201]  (hidden comment: CL03A105MP3NSNC)
C309  ValueDisplayed: 0.1µF  [0201]  (hidden comment: GRM033C71A104KE14D)
C310  ValueDisplayed: 0.1µF  [0201]  (hidden comment: GRM033C71A104KE14D)
C311  ValueDisplayed: 0.1µF  [0201]  (hidden comment: GRM033C71A104KE14D)
C312  ValueDisplayed: 10µF  [0402_070]  (hidden comment: GRM155R61A106ME21D)
C313  ValueDisplayed: 1µF  [0201]  (hidden comment: CL03A105MP3NSNC)
C314  ValueDisplayed: 0.1µF  [0201]  (hidden comment: GRM033C71A104KE14D)
C315  ValueDisplayed: 0.1µF  [0201]  (hidden comment: GRM033C71A104KE14D)
C316  ValueDisplayed: 10µF  [0402_070]  (hidden comment: GRM155R61A106ME21D)
C317  ValueDisplayed: 1µF  [0201]  (hidden comment: CL03A105MP3NSNC)
C318  ValueDisplayed: 10µF  [0402_070]  (hidden comment: GRM155R61A106ME21D)
C319  ValueDisplayed: 1µF  [0201]  (hidden comment: CL03A105MP3NSNC)
C320  ValueDisplayed: 0.1µF  [0201]  (hidden comment: GRM033C71A104KE14D)
C321  ValueDisplayed: 0.1µF  [0201]  (hidden comment: GRM033C71A104KE14D)
C322  ValueDisplayed: 0.1µF  [0201]  (hidden comment: GRM033C71A104KE14D)
C323  ValueDisplayed: 1µF  [0201]  (hidden comment: CL03A105MP3NSNC)
C324  ValueDisplayed: 10µF  [0402_070]  (hidden comment: GRM155R61A106ME21D)
C325  ValueDisplayed: 1µF  [0201]  (hidden comment: CL03A105MP3NSNC)
C326  ValueDisplayed: 0.1µF  [0201]  (hidden comment: GRM033C71A104KE14D)
C327  ValueDisplayed: 10µF  [0402_070]  (hidden comment: GRM155R61A106ME21D)
C328  ValueDisplayed: 1µF  [0201]  (hidden comment: CL03A105MP3NSNC)
C329  ValueDisplayed: 0.1µF  [0201]  (hidden comment: GRM033C71A104KE14D)
C330  ValueDisplayed: 10µF  [0402_070]  (hidden comment: GRM155R61A106ME21D)
C331  ValueDisplayed: 1µF  [0201]  (hidden comment: CL03A105MP3NSNC)
C332  ValueDisplayed: 0.1µF  [0201]  (hidden comment: GRM033C71A104KE14D)
C333  ValueDisplayed: 0.1µF  [0201]  (hidden comment: GRM033C71A104KE14D)
C334  ValueDisplayed: 0.1µF  [0201]  (hidden comment: GRM033C71A104KE14D)
C335  ValueDisplayed: 10µF  [0402_070]  (hidden comment: GRM155R61A106ME21D)
C336  ValueDisplayed: 1µF  [0201]  (hidden comment: CL03A105MP3NSNC)
C337  ValueDisplayed: 0.1µF  [0201]  (hidden comment: GRM033C71A104KE14D)
C338  ValueDisplayed: 0.1µF  [0201]  (hidden comment: GRM033C71A104KE14D)
C339  ValueDisplayed: 0.1µF  [0201]  (hidden comment: GRM033C71A104KE14D)
C340  ValueDisplayed: 0.1µF  [0201]  (hidden comment: GRM033C71A104KE14D)
C341  ValueDisplayed: 0.1µF  [0201]  (hidden comment: GRM033C71A104KE14D)
U6  AFE7444IABJ  [ABJ0400A]  (part F of 6)

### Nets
DVDD_2: C255.1 C256.1 C257.1 C258.1 C259.1 C260.1 C261.1 C262.1 C263.1 C264.1 C265.1 C333.1 C334.1 U6.G13(DVDD) U6.H6(DVDD) U6.H7(DVDD) U6.H13(DVDD) U6.J12(DVDD) U6.J13(DVDD) U6.K6(DVDDPR) U6.K7(DVDDPR) U6.K8(DVDDAR) U6.K9(DVDD) U6.K10(VPP) U6.K11(DVDD) U6.K12(DVDD) U6.K13(DVDD) U6.L6(DVDD) U6.L7(VNWA) U6.L8(DVDD) U6.L9(DVDD) U6.L10(DVDD) U6.L11(DVDD) U6.L12(DVDD) U6.L13(DVDD) U6.M12(DVDD) U6.M13(DVDD) U6.N6(DVDD) U6.N7(DVDD) U6.N13(DVDD) U6.P13(DVDD)
GND: C255.2 C256.2 C257.2 C258.2 C259.2 C260.2 C261.2 C262.2 C263.2 C264.2 C265.2 C266.2 C267.2 C268.2 C269.2 C270.2 C271.2 C272.2 C273.2 C274.2 C275.2 C276.2 C277.2 C278.2 C279.2 C280.2 C281.2 C282.2 C283.2 C284.2 C285.2 C286.2 C287.2 C288.2 C289.2 C290.2 C291.2 C292.2 C293.2 C294.2 C295.2 C296.2 C297.2 C298.2 C299.2 C300.2 C301.2 C302.2 C303.2 C304.2 C305.2 C306.2 C307.2 C308.2 C309.2 C310.2 C311.2 C312.2 C313.2 C314.2 C315.2 C316.2 C317.2 C318.2 C319.2 C320.2 C321.2 C322.2 C323.2 C324.2 C325.2 C326.2 C327.2 C328.2 C329.2 C330.2 C331.2 C332.2 C333.2 C334.2 C335.2 C336.2 C337.2 C338.2 C339.2 C340.2 C341.2
RX_1.2V_2: C289.1 C290.1 C291.1 C292.1 C293.1 C294.1 C295.1 C296.1 C297.1 C298.1 U6.F5(RX1P2V) U6.F6(RX1P2V) U6.F7(RX1P2V) U6.F8(RX1P2V) U6.F9(RX1P2V) U6.F10(RX1P2V) U6.G6(RX1P2V) U6.G7(RX1P2V) U6.G8(RX1P2V) U6.P6(RX1P2V) U6.P7(RX1P2V) U6.P8(RX1P2V) U6.R5(RX1P2V) U6.R6(RX1P2V) U6.R7(RX1P2V) U6.R8(RX1P2V) U6.R9(RX1P2V) U6.R10(RX1P2V)
RX_1.8V_2: C273.1 C274.1 C275.1 C276.1 C277.1 C278.1 C279.1 C280.1 C281.1 C282.1 U6.C5(RX1P8V) U6.C6(RX1P8V) U6.D5(RX1P8V) U6.D6(RX1P8V) U6.D9(RX1P8V) U6.D10(RX1P8V) U6.E5(RX1P8V) U6.E6(RX1P8V) U6.E9(RX1P8V) U6.E10(RX1P8V) U6.T5(RX1P8V) U6.T6(RX1P8V) U6.T9(RX1P8V) U6.T10(RX1P8V) U6.U5(RX1P8V) U6.U6(RX1P8V) U6.U9(RX1P8V) U6.U10(RX1P8V) U6.V5(RX1P8V) U6.V6(RX1P8V)
VDDA_1.0V_2: C283.1 C284.1 C285.1 U6.F15(VDDATXAB) U6.R15(VDDATXCD)
VDDA_1.8V_2: C286.1 C287.1 C288.1 U6.G18(VDDA18TXAB) U6.H18(VDDA18TXAB) U6.N18(VDDA18TXCD) U6.P18(VDDA18TXCD)
VDDA_SERDES_1.0V_2: C327.1 C328.1 C329.1 U6.D3(VDDA) U6.D4(VDDA) U6.U3(VDDA) U6.U4(VDDA)
VDDCLK_1.0V_2: C312.1 C313.1 C314.1 C315.1 U6.G16(VDDCLK) U6.H16(VDDCLK) U6.K17(VDDCLK) U6.N16(VDDCLK) U6.P16(VDDCLK)
VDDE_2: C335.1 C336.1 C337.1 C338.1 C339.1 C340.1 C341.1 U6.F14(VDDETXAB) U6.G14(VDDETXAB) U6.H14(VDDETXAB) U6.J14(VDDETXAB) U6.M14(VDDETXCD) U6.N14(VDDETXCD) U6.P14(VDDETXCD) U6.R14(VDDETXCD)
VDDGPIO_1.8V_2: C323.1 U6.D17(VDDGPIO18)
VDDL1_1.0V_2: C307.1 C308.1 C309.1 C310.1 C311.1 U6.G15(VDDL1TXAB) U6.H15(VDDL1TXAB) U6.N15(VDDL1TXCD) U6.P15(VDDL1TXCD)
VDDL2_1.0V_2: C318.1 C319.1 C320.1 C321.1 C322.1 U6.G17(VDDL2TXAB) U6.H17(VDDL2TXAB) U6.N17(VDDL2TXCD) U6.P17(VDDL2TXCD)
VDDPLL_1.0V_2: C299.1 C300.1 U6.K18(VDDPLL)
VDDPLL_1.8V_2: C301.1 C302.1 U6.L18(VDDAPLL18)
VDDR_SERDES_1.5V_2: C324.1 C325.1 C326.1 U6.F3(VDDR) U6.F4(VDDR) U6.R3(VDDR) U6.R4(VDDR)
VDDT_SERDES_1.0V_2: C330.1 C331.1 C332.1 U6.H3(VDDT) U6.H4(VDDT) U6.N3(VDDT) U6.N4(VDDT)
VDDTX_1.0V_2: C316.1 C317.1 U6.J15(VDDTX)
VDDTX_1.8V_2: C305.1 C306.1 U6.K16(VDDTX18)
VDDVCO_1.8V_2: C303.1 C304.1 U6.L17(VDDAVCO18) U6.M17(VDDAVCO18)
VEE_2: C266.1 C267.1 C268.1 C269.1 C270.1 C271.1 C272.1 U6.D18(VEETXAB) U6.E17(VEETXAB) U6.E18(VEETXAB) U6.T17(VEETXCD) U6.T18(VEETXCD) U6.U17(VEETXCD)

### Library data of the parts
C255 C266 C273 C283 C286 C289 C299 C301 C303 C305 C307 C312 C316 C318 C324 C327 C330 C335 = GRM155R61A106ME21D: CAP, CERM, 10 µF, 10 V,+/- 20%, X5R, 0402; Manufacturer: MuRata; Polarized: N; CompType: Capacitor; Value: 10uF; U/M: EA; Cap_F: 0.00001; Tolerance_%: 20; VDC_V: 10; Value2: 10V; TaMin_C: -55; TaMax_C: 85; Cap_Case: 0402; SizeArea_mm2: 0.5; SizeAreaWB_mm2: 3; SizeX_mm: 1; SizeZ_mm: 0.7; AEC Category: Q200; Green_Lifecycle: Not Set; Green_REACh: Incomplete
C256 C267 C274 C284 C287 C290 C300 C302 C304 C306 C308 C313 C317 C319 C323 C325 C328 C331 C336 = CL03A105MP3NSNC: CAP, CERM, 1 µF, 10 V,+/- 20%, X5R, 0201; Manufacturer: Samsung Electro-Mechanics; Polarized: N; CompType: Capacitor; Value: 1uF; U/M: EA; Cap_F: 0.000001; Tolerance_%: 20; VDC_V: 10; Value2: 10V; TaMin_C: -55; TaMax_C: 85; SizeArea_mm2: 0.18; SizeAreaWB_mm2: 2.08; SizeX_mm: 0.6; SizeY_mm: 0.3; SizeZ_mm: 0.26; AEC Category: Q200; Green_Lifecycle: Active; Green_REACh: Passed
C257-C265 C268-C272 C275-C282 C285 C288 C291-C298 C309-C311 C314 C315 C320-C322 C326 C329 C332-C334 C337-C341 = GRM033C71A104KE14D: CAP, CERM, 0.1 µF, 10 V, +/- 10%, X7S, 0201; Manufacturer: MuRata; Polarized: N; CompType: Capacitor; Value: 0.1uF; U/M: EA; Cap_F: 0.0000001; Tolerance_%: 10; Value1: Unknown; Value2: 10V; TaMin_C: -55; TaMax_C: 125; SizeArea_mm2: 0.18; SizeAreaWB_mm2: 2.08; SizeX_mm: 0.6; SizeY_mm: 0.3; SizeZ_mm: 0.26; AEC Category: Q200
U6 = CMP-0084351-1: Quad-Channel RF Sampling Transceiver with 14-bit 9-GSPS DACs and 14-bit 3-GSPS ADCs, ABJ0400A (DSBGA-400); Manufacturer: Texas Instruments; SizeY_mm: 17; AEC Qualified: N; CompType: IC; SizeZ_mm: 2.65; SizeAreaWB_mm2: 361; AEC Category: Q200; SizeArea_mm2: 289

## Sheet AFE2-RX-TX-INTERFACE.SchDoc
size 431 x 279 mm; Date: Not shown in title block; ApprovedBy: Not shown in title block; CheckedBy: Not shown in title block; Author: Not shown in title block; CompanyName: Not shown in title block; DrawnBy: Avinash N; Engineer: Not shown in title block; Organization: Not shown in title block; Address1: Not shown in title block; Address2: Not shown in title block; Address3: Not shown in title block; Address4: Not shown in title block; DocumentNumber: 1; Revision: Use project parameter SCH_Rev; SheetNumber: 18; SheetTotal: 32; PageSetup: Record=PageOptions¦CenterHorizontal=True¦CenterVertical=True¦PrintScale=1.00¦XCorrection=1.00¦YCorrection=1.00¦PrintKind=0¦BorderSize=5000000¦LeftOffset=0¦BottomOffset=0¦Orientation=2¦PaperLength=1000¦PaperWidth=1000¦Scale=100¦PaperSource=15¦PrintQuality=600¦MediaType=1¦DitherType=10¦PaperKind=Letter¦PrintScaleMode=1
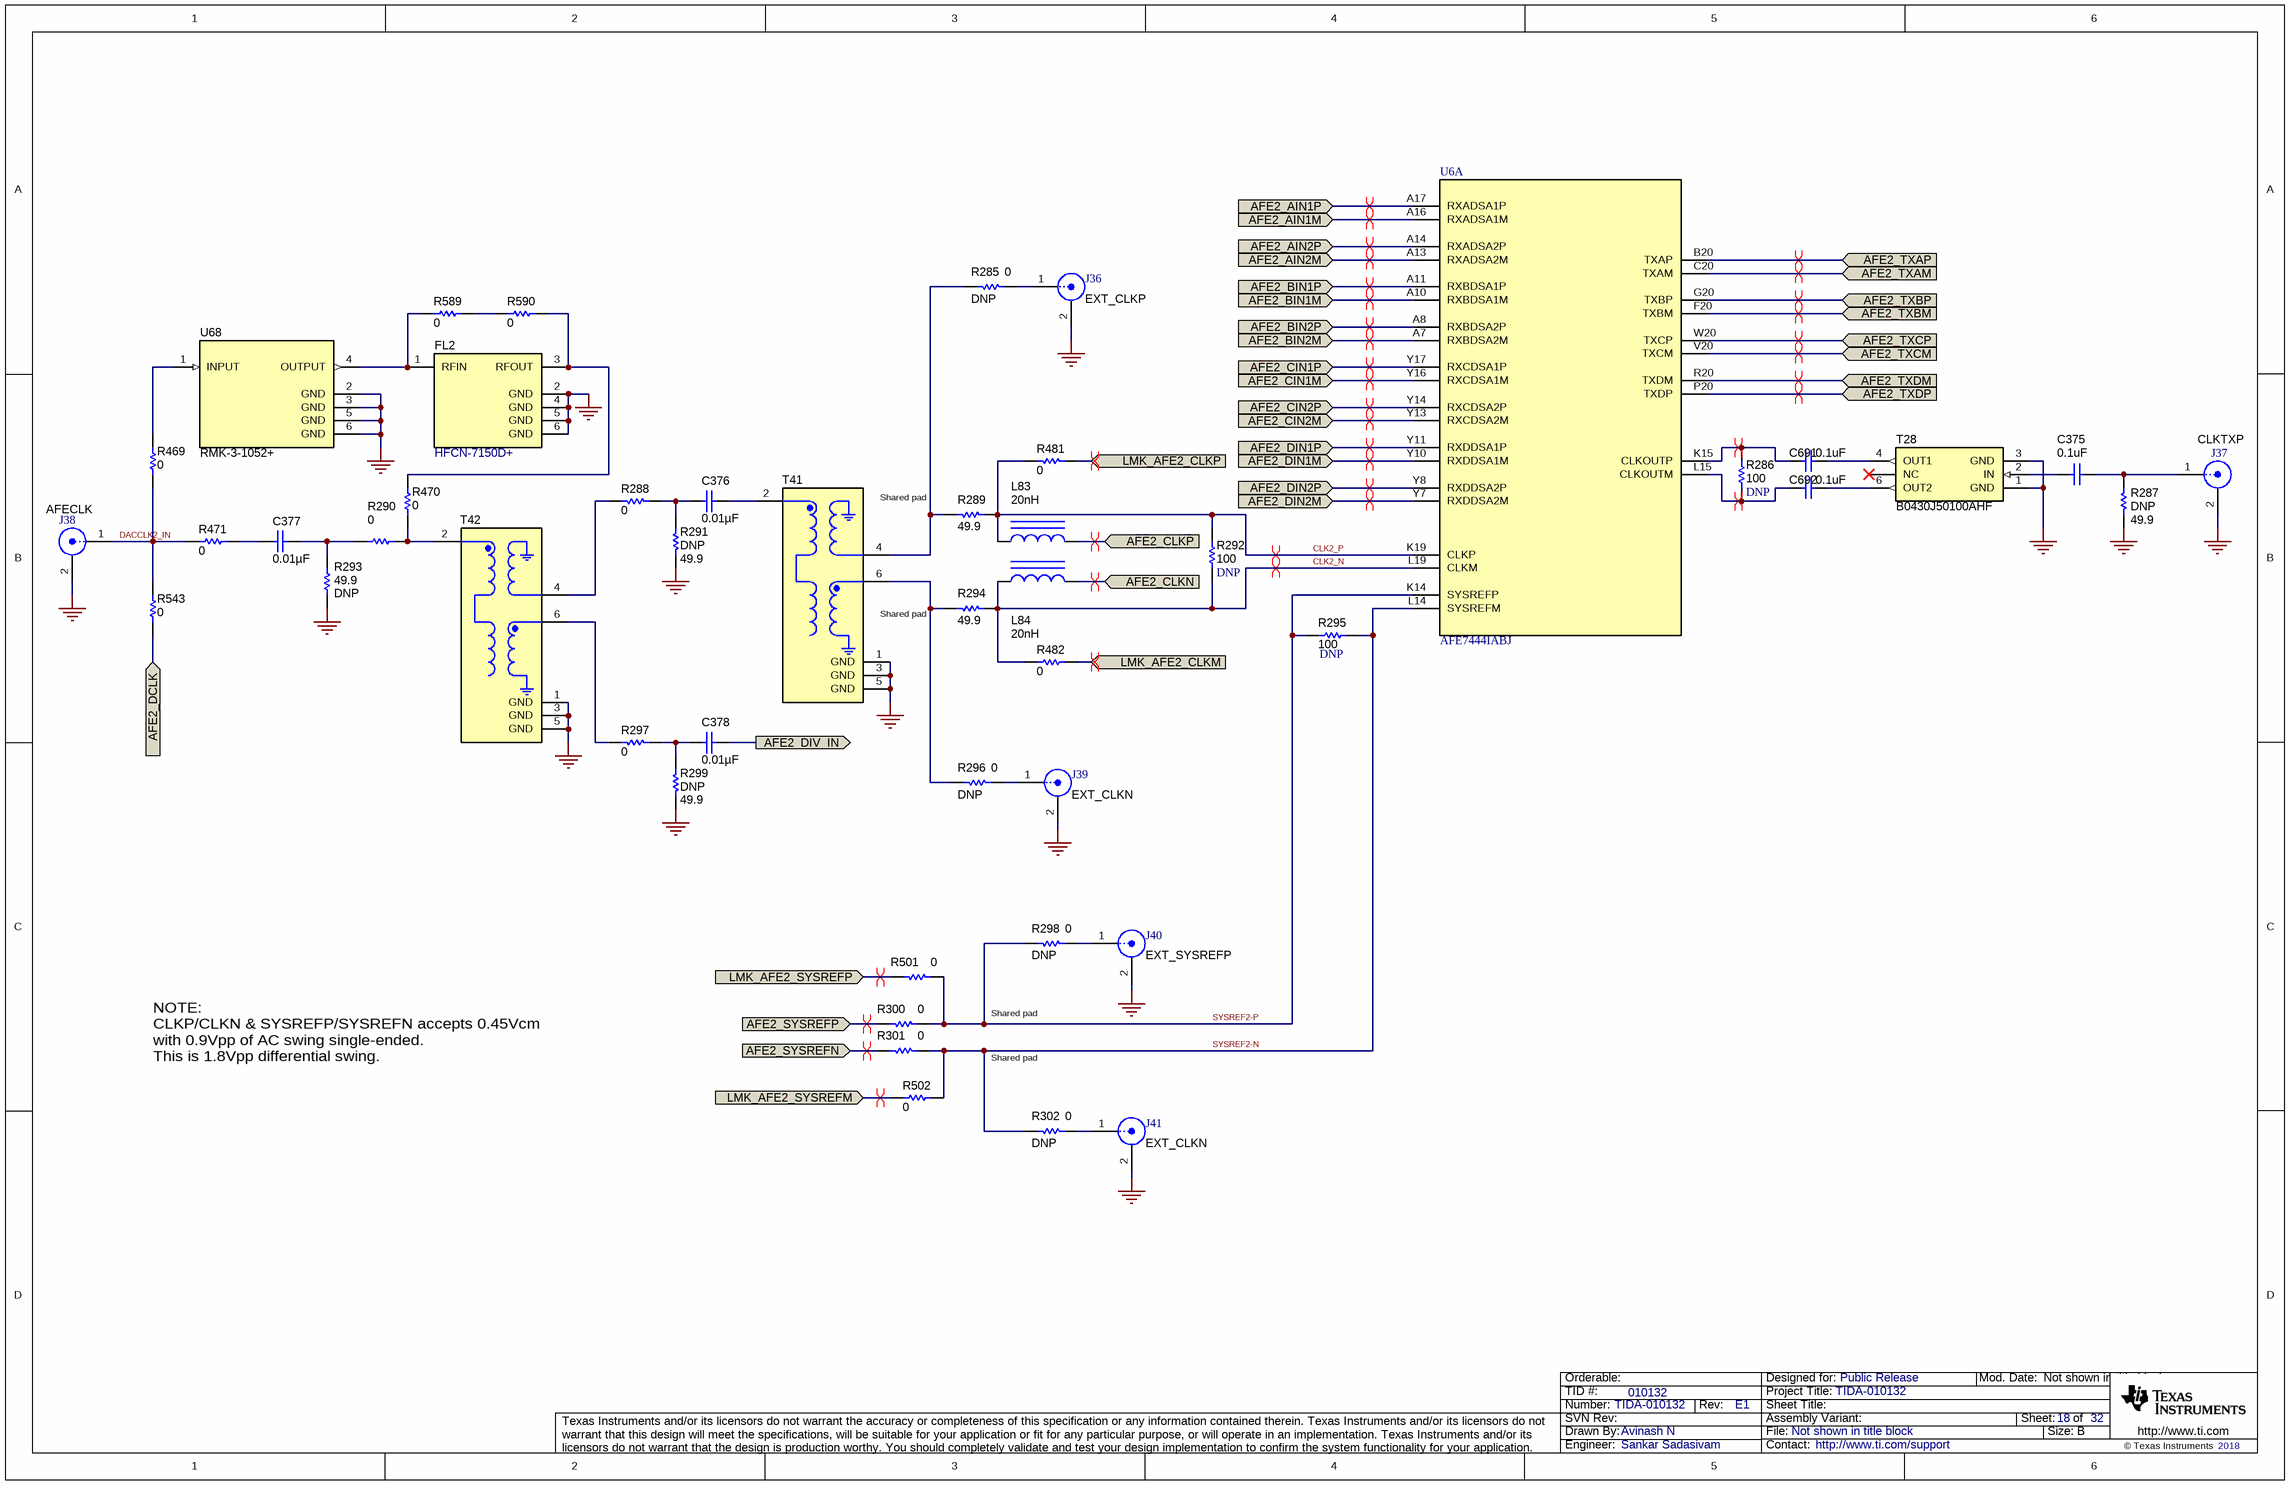
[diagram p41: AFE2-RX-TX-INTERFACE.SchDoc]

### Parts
C375  ValueDisplayed: 0.1uF  [0402_065]  (hidden comment: 550L104KCAT)
C376  ValueDisplayed: 0.01µF  [0402]  (hidden comment: GRM155R71H103KA88D)
C377  ValueDisplayed: 0.01µF  [0402]  (hidden comment: GRM155R71H103KA88D)
C378  ValueDisplayed: 0.01µF  [0402]  (hidden comment: GRM155R71H103KA88D)
C691  ValueDisplayed: 0.1uF  [0402_065]  (hidden comment: 550L104KCAT)
C692  ValueDisplayed: 0.1uF  [0402_065]  (hidden comment: 550L104KCAT)
FL2  HFCN-7150D+  [FV1206-1]
J36  EXT_CLKP  [Molex_0853050232]
J37  CLKTXP  [Molex_0853050232]
J38  AFECLK  [Molex_0853050232]
J39  EXT_CLKN  [Molex_0853050232]
J40  EXT_SYSREFP  [Molex_0853050232]
J41  EXT_CLKN  [Molex_0853050232]
L83  ValueDisplayed: 20nH  [LQG15WZ_02]  (hidden comment: LQG15WZ20NH02D)
L84  ValueDisplayed: 20nH  [LQG15WZ_02]  (hidden comment: LQG15WZ20NH02D)
R285  DNP  ValueDisplayed: 0  [0402]
R286  ValueDisplayed: 100  [0201]  (hidden comment: ERJ-1GEF1000C)
R287  DNP  ValueDisplayed: 49.9  [0402]
R288  ValueDisplayed: 0  [0402]  (hidden comment: ERJ-2GE0R00X)
R289  ValueDisplayed: 49.9  [0402]  (hidden comment: ERJ-2RKF49R9X)
R290  ValueDisplayed: 0  [0402]  (hidden comment: ERJ-2GE0R00X)
R291  DNP  ValueDisplayed: 49.9  [0402]
R292  ValueDisplayed: 100  [0201]  (hidden comment: ERJ-1GEF1000C)
R293  DNP  ValueDisplayed: 49.9  [0402]
R294  ValueDisplayed: 49.9  [0402]  (hidden comment: ERJ-2RKF49R9X)
R295  ValueDisplayed: 100  [0201]  (hidden comment: ERJ-1GEF1000C)
R296  DNP  ValueDisplayed: 0  [0402]
R297  ValueDisplayed: 0  [0402]  (hidden comment: ERJ-2GE0R00X)
R298  DNP  ValueDisplayed: 0  [0402]
R299  DNP  ValueDisplayed: 49.9  [0402]
R300  ValueDisplayed: 0  [0402]  (hidden comment: ERJ-2GE0R00X)
R301  ValueDisplayed: 0  [0402]  (hidden comment: ERJ-2GE0R00X)
R302  DNP  ValueDisplayed: 0  [0402]
R469  ValueDisplayed: 0  [0402]  (hidden comment: ERJ-2GE0R00X)
R470  ValueDisplayed: 0  [0402]  (hidden comment: ERJ-2GE0R00X)
R471  ValueDisplayed: 0  [0402]  (hidden comment: ERJ-2GE0R00X)
R481  ValueDisplayed: 0  [0402]  (hidden comment: ERJ-2GE0R00X)
R482  ValueDisplayed: 0  [0402]  (hidden comment: ERJ-2GE0R00X)
R501  ValueDisplayed: 0  [0402]  (hidden comment: ERJ-2GE0R00X)
R502  ValueDisplayed: 0  [0402]  (hidden comment: ERJ-2GE0R00X)
R543  ValueDisplayed: 0  [0402]  (hidden comment: ERJ-2GE0R00X)
R589  ValueDisplayed: 0  [0402]  (hidden comment: ERJ-2GE0R00X)
R590  ValueDisplayed: 0  [0402]  (hidden comment: ERJ-2GE0R00X)
T28  B0430J50100AHF  [B0430J50100AHF]
T41  NCR2-113+  [MNC_NF1846-1]  (value not drawn)
T42  NCR2-113+  [MNC_NF1846-1]  (value not drawn)
U6  AFE7444IABJ  [ABJ0400A]  (part A of 6)
U68  RMK-3-1052+  [Minicircuits_TT1224]

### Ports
AFE2_AIN1M (in), AFE2_AIN1P (in), AFE2_AIN2M (in), AFE2_AIN2P (in), AFE2_BIN1M (in), AFE2_BIN1P (in), AFE2_BIN2M (in), AFE2_BIN2P (in), AFE2_CIN1M (in), AFE2_CIN1P (in), AFE2_CIN2M (in), AFE2_CIN2P (in), AFE2_CLKN (in), AFE2_CLKP (in), AFE2_DCLK (in), AFE2_DIN1M (in), AFE2_DIN1P (in), AFE2_DIN2M (in), AFE2_DIN2P (in), AFE2_DIV_IN (out), AFE2_SYSREFN (in), AFE2_SYSREFP (in), AFE2_TXAM (in), AFE2_TXAP (in), AFE2_TXBM (in), AFE2_TXBP (in), AFE2_TXCM (in), AFE2_TXCP (in), AFE2_TXDM (in), AFE2_TXDP (in), LMK_AFE2_CLKM (in), LMK_AFE2_CLKP (in), LMK_AFE2_SYSREFM (in), LMK_AFE2_SYSREFP (in)

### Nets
GND: FL2.2(GND) FL2.4(GND) FL2.5(GND) FL2.6(GND) J36.2 J37.2 J38.2 J39.2 J40.2 J41.2 R287.1 R291.1 R293.1 R299.1 T28.1(GND) T28.3(GND) T41.1(GND) T41.3(GND) T41.5(GND) T42.1(GND) T42.3(GND) T42.5(GND) U68.2(GND) U68.3(GND) U68.5(GND) U68.6(GND)
AFE2_AIN1M: U6.A16(RXADSA1M) ; port AFE2_AIN1M
AFE2_AIN1P: U6.A17(RXADSA1P) ; port AFE2_AIN1P
AFE2_AIN2M: U6.A13(RXADSA2M) ; port AFE2_AIN2M
AFE2_AIN2P: U6.A14(RXADSA2P) ; port AFE2_AIN2P
AFE2_BIN1M: U6.A10(RXBDSA1M) ; port AFE2_BIN1M
AFE2_BIN1P: U6.A11(RXBDSA1P) ; port AFE2_BIN1P
AFE2_BIN2M: U6.A7(RXBDSA2M) ; port AFE2_BIN2M
AFE2_BIN2P: U6.A8(RXBDSA2P) ; port AFE2_BIN2P
AFE2_CIN1M: U6.Y16(RXCDSA1M) ; port AFE2_CIN1M
AFE2_CIN1P: U6.Y17(RXCDSA1P) ; port AFE2_CIN1P
AFE2_CIN2M: U6.Y13(RXCDSA2M) ; port AFE2_CIN2M
AFE2_CIN2P: U6.Y14(RXCDSA2P) ; port AFE2_CIN2P
AFE2_CLKN: L84.2 ; port AFE2_CLKN
AFE2_CLKP: L83.2 ; port AFE2_CLKP
AFE2_DCLK: R543.1 ; port AFE2_DCLK
AFE2_DIN1M: U6.Y10(RXDDSA1M) ; port AFE2_DIN1M
AFE2_DIN1P: U6.Y11(RXDDSA1P) ; port AFE2_DIN1P
AFE2_DIN2M: U6.Y7(RXDDSA2M) ; port AFE2_DIN2M
AFE2_DIN2P: U6.Y8(RXDDSA2P) ; port AFE2_DIN2P
AFE2_DIV_IN: C378.1 ; port AFE2_DIV_IN
AFE2_SYSREFN: R301.2 ; port AFE2_SYSREFN
AFE2_SYSREFP: R300.2 ; port AFE2_SYSREFP
AFE2_TXAM: U6.C20(TXAM) ; port AFE2_TXAM
AFE2_TXAP: U6.B20(TXAP) ; port AFE2_TXAP
AFE2_TXBM: U6.F20(TXBM) ; port AFE2_TXBM
AFE2_TXBP: U6.G20(TXBP) ; port AFE2_TXBP
AFE2_TXCM: U6.V20(TXCM) ; port AFE2_TXCM
AFE2_TXCP: U6.W20(TXCP) ; port AFE2_TXCP
AFE2_TXDM: U6.R20(TXDM) ; port AFE2_TXDM
AFE2_TXDP: U6.P20(TXDP) ; port AFE2_TXDP
CLK2_N: L84.1 R292.1 R294.1 R482.2 U6.L19(CLKM)
CLK2_P: L83.1 R289.1 R292.2 R481.2 U6.K19(CLKP)
DACCLK2_IN: J38.1 R469.1 R471.2 R543.2
LMK_AFE2_CLKM: R482.1 ; port LMK_AFE2_CLKM
LMK_AFE2_CLKP: R481.1 ; port LMK_AFE2_CLKP
LMK_AFE2_SYSREFM: R502.2 ; port LMK_AFE2_SYSREFM
LMK_AFE2_SYSREFP: R501.2 ; port LMK_AFE2_SYSREFP
SYSREF2-N: R295.2 R301.1 R302.2 R502.1 U6.L14(SYSREFM)
SYSREF2-P: R295.1 R298.2 R300.1 R501.1 U6.K14(SYSREFP)
NetC375_1: C375.1 J37.1 R287.2
NetC375_2: C375.2 T28.2(IN)
NetC376_1: C376.1 T41.2
NetC376_2: C376.2 R288.1 R291.2
NetC377_1: C377.1 R290.1 R293.2
NetC377_2: C377.2 R471.1
NetC378_2: C378.2 R297.1 R299.2
NetC691_1: C691.1 T28.4(OUT1)
NetC691_2: C691.2 R286.2 U6.K15(CLKOUTP)
NetC692_1: C692.1 T28.6(OUT2)
NetC692_2: C692.2 R286.1 U6.L15(CLKOUTM)
NetFL2_1: FL2.1(RFIN) R589.2 U68.4(OUTPUT)
NetFL2_3: FL2.3(RFOUT) R470.2 R590.1
NetJ36_1: J36.1 R285.1
NetJ39_1: J39.1 R296.1
NetJ40_1: J40.1 R298.1
NetJ41_1: J41.1 R302.1
NetR285_2: R285.2 R289.2 T41.4
NetR288_2: R288.2 T42.4
NetR290_2: R290.2 R470.1 T42.2
NetR294_2: R294.2 R296.2 T41.6
NetR297_2: R297.2 T42.6
NetR469_2: R469.2 U68.1(INPUT)
NetR589_1: R589.1 R590.2

Not connected (* = marked no-connect by the designer): T28 5(NC)*

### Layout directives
differential pair: AFE2_AIN1M, AFE2_AIN1P, AFE2_AIN2M, AFE2_AIN2P, AFE2_BIN1M, AFE2_BIN1P, AFE2_BIN2M, AFE2_BIN2P, AFE2_CIN1M, AFE2_CIN1P, AFE2_CIN2M, AFE2_CIN2P, AFE2_CLKN, AFE2_CLKP, AFE2_DIN1M, AFE2_DIN1P, AFE2_DIN2M, AFE2_DIN2P, AFE2_SYSREFN, AFE2_SYSREFP, AFE2_TXAM, AFE2_TXAP, AFE2_TXBM, AFE2_TXBP, AFE2_TXCM, AFE2_TXCP, AFE2_TXDM, AFE2_TXDP, CLK2_N, CLK2_P, LMK_AFE2_CLKM, LMK_AFE2_CLKP, LMK_AFE2_SYSREFM, LMK_AFE2_SYSREFP, NetC691_2, NetC692_2

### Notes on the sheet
- (near T41) Shared pad
- Shared pad
- NOTE:
  CLKP/CLKN & SYSREFP/SYSREFN accepts 0.45Vcm
  with 0.9Vpp of AC swing single-ended.
  This is 1.8Vpp differential swing.

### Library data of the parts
C375 C691 C692 = CMP-0006211-2: CAP, CERM, 0.1 uF, 16 V, +/- 10%, Unknown, 0402; Manufacturer: AT Ceramics; TaMin_C: -55°C; Polarized: N; SizeAreaWB_mm2: 3; U/M: EA; Value: 0.1uF; TaMax_C: 125°C; SizeZ_mm: 0.65; SizeX_mm: 1; SizeY_mm: 0.5; Cap_Case: 0402; Value2: 16V; Cap_F: 100nF; AEC Category: Q200
C376-C378 = GRM155R71H103KA88D: CAP, CERM, 0.01 µF, 50 V,+/- 10%, X7R, 0402; Manufacturer: MuRata; Polarized: N; CompType: Capacitor; Value: 0.01uF; U/M: EA; Cap_F: 0.00000001; Tolerance_%: 10; Value1: Unknown; VDC_V: 50; Value2: 50V; TaMin_C: -55; TaMax_C: 125; SizeArea_mm2: 0.5; SizeAreaWB_mm2: 3; SizeX_mm: 1; SizeZ_mm: 0.6; AEC Category: Q200; Green_Lifecycle: Active; Green_REACh: Passed
FL2 = CMP-0001869-2: High Pass Filter, 50 Ohm, 79000 to 11000 MHz, FV1206-1; PartNumber: HFCN-3100D+; Manufacturer: Minicircuits; SizeZ_mm: 1.067; SizeX_mm: 3.2; SizeY_mm: 1.6; SizeAreaWB_mm2: 10.92; SizeArea_mm2: 5.12
J36-J41 = CMP-0077224-1: Plug, 50 Ohm, Straight, SMT; PartNumber: 0853050232; Manufacturer: Molex; Cert_UL: Y; ContactFinish: Gold; CT: False; Gender: Male; Voltage_V: 335V
L83 L84 = CMP-0080189-3: Inductor, Multilayer, Air Core, 20 nH, 0.26 A, 1.1 ohm, AEC-Q200 Grade 1, SMD; Manufacturer: MuRata; Irms: 0.26A @ 25C rise; SizeAreaWB_mm2: 3.2; DCR_ohm: 1.1; Value1: 1.1 ohm; Value: 20nH; Imax_A: 2.6dA; SizeZ_mm: 0.6; SizeX_mm: 1; Value2: 0.26A; AEC Qualified: Y; AEC Category: Q200
R285 R288 R290 R296-R298 R300-R302 R469-R471 R481 R482 R501 R502 R543 R589 R590 = ERJ-2GE0R00X: RES, 0, 5%, 0.063 W, 0402; Manufacturer: Panasonic; CompType: Resistor; Value: 0; Value_Code: 0000; Tolerance_%: 5; Power_W: 0.063; Value2: 0.063W; VDC_V: 50; TempCo: 600 ppm/C; SizeArea_mm2: 0.5; SizeX_mm: 1; SizeZ_mm: 0.6; EIA_Code: E24; U/M: EA; AEC Category: Q200; Green_Lifecycle: Active; Green_REACh: Passed
R286 R292 R295 = ERJ-1GEF1000C: RES, 100, 1%, 0.05 W, 0201; Manufacturer: Panasonic; CompType: Resistor; Value: 100; Value_Code: 100R; Tolerance_%: 1; Power_W: 0.05; Value2: 0.05W; VDC_V: 25; TempCo: 200 ppm/C; SizeArea_mm2: 0.18; SizeX_mm: 0.6; SizeY_mm: 0.3; SizeZ_mm: 0.26; EIA_Code: E96; U/M: EA; AEC Category: Q200
R287 R289 R291 R293 R294 R299 = ERJ-2RKF49R9X: RES, 49.9, 1%, 0.1 W, AEC-Q200 Grade 0, 0402; Manufacturer: Panasonic; CompType: Resistor; Value: 49.9; Value_Code: 49R9; Tolerance_%: 1; Power_W: 0.1; Value2: 0.1W; VDC_V: 50; TempCo: 100 ppm/C; SizeArea_mm2: 0.5; SizeZ_mm: 0.6; EIA_Code: E96; U/M: EA; AEC Category: Q200; AEC Qualified: Y; AEC Grade: 0; Green_Lifecycle: Active; Green_REACh: Passed
T28 = CMP-0030061-1: Transformer, Multi-layer balun, SMD; Manufacturer: Anaren; Green_REACh: Incomplete; Green_Lifecycle: Not Set
T41 T42 = NCR2-123+: RF Transformer, 50 Ohm, 3W, SMT; Manufacturer: Minicircuits; SymbolCreator: Altium; SizeAreaWB_mm2: 10.5049; SizeArea_mm2: 5.0049; SizeX_mm: 2.01; SizeY_mm: 2.49; SizeZ_mm: 0.89
U6 = CMP-0084351-1: as U6 on sheet AFE2-POWER
U68 = CMP-0084474-1: Frequency Multiplier, 50Ω, Output 6600 to 10500 MHz, SMD; Manufacturer: Minicircuits; SizeZ_mm: 4.06; SizeAreaWB_mm2: 82.4145; SizeArea_mm2: 49.9745; SizeX_mm: 7.87; SizeY_mm: 6.35

## Sheet AFE2-GROUND.SchDoc
size 431 x 279 mm; Date: Not shown in title block; ApprovedBy: Not shown in title block; CheckedBy: Not shown in title block; Author: Not shown in title block; CompanyName: Not shown in title block; DrawnBy: Avinash N; Engineer: Not shown in title block; Organization: Not shown in title block; Address1: Not shown in title block; Address2: Not shown in title block; Address3: Not shown in title block; Address4: Not shown in title block; DocumentNumber: 1; Revision: Use project parameter SCH_Rev; SheetNumber: 22; SheetTotal: 32; PageSetup: Record=PageOptions¦CenterHorizontal=True¦CenterVertical=True¦PrintScale=1.00¦XCorrection=1.00¦YCorrection=1.00¦PrintKind=0¦BorderSize=5000000¦LeftOffset=0¦BottomOffset=0¦Orientation=2¦PaperLength=1000¦PaperWidth=1000¦Scale=100¦PaperSource=15¦PrintQuality=600¦MediaType=1¦DitherType=10¦PaperKind=Letter¦PrintScaleMode=1
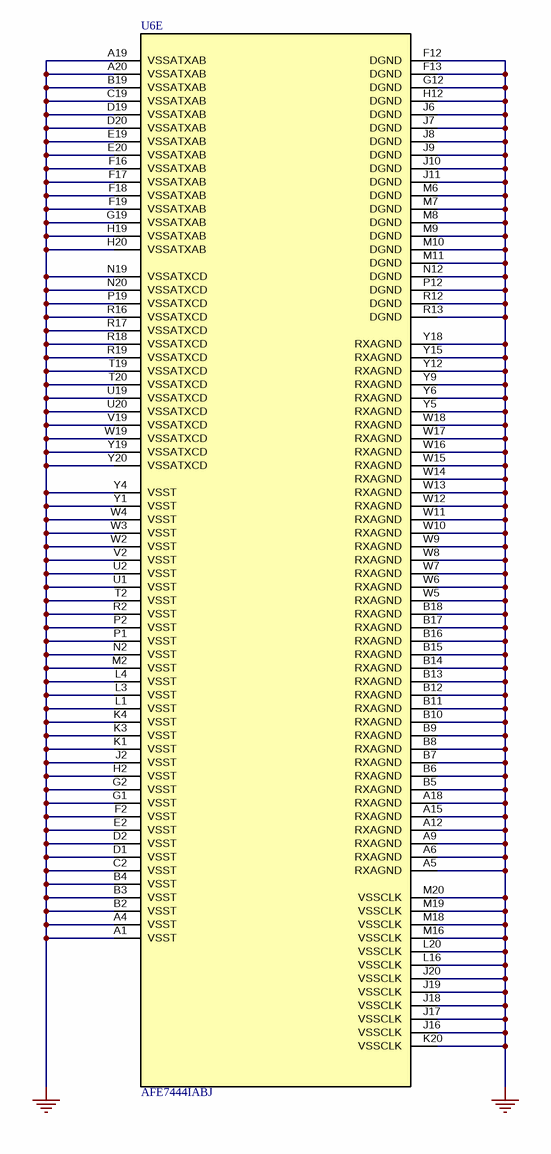
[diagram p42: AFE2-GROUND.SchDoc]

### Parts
U6  AFE7444IABJ  [ABJ0400A]  (part E of 6)

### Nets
GND: U6.A1(VSST) U6.A4(VSST) U6.A5(RXAGND) U6.A6(RXAGND) U6.A9(RXAGND) U6.A12(RXAGND) U6.A15(RXAGND) U6.A18(RXAGND) U6.A19(VSSATXAB) U6.A20(VSSATXAB) U6.B2(VSST) U6.B3(VSST) U6.B4(VSST) U6.B5(RXAGND) U6.B6(RXAGND) U6.B7(RXAGND) U6.B8(RXAGND) U6.B9(RXAGND) U6.B10(RXAGND) U6.B11(RXAGND) U6.B12(RXAGND) U6.B13(RXAGND) U6.B14(RXAGND) U6.B15(RXAGND) U6.B16(RXAGND) U6.B17(RXAGND) U6.B18(RXAGND) U6.B19(VSSATXAB) U6.C2(VSST) U6.C19(VSSATXAB) U6.D1(VSST) U6.D2(VSST) U6.D19(VSSATXAB) U6.D20(VSSATXAB) U6.E2(VSST) U6.E19(VSSATXAB) U6.E20(VSSATXAB) U6.F2(VSST) U6.F12(DGND) U6.F13(DGND) U6.F16(VSSATXAB) U6.F17(VSSATXAB) U6.F18(VSSATXAB) U6.F19(VSSATXAB) U6.G1(VSST) U6.G2(VSST) U6.G12(DGND) U6.G19(VSSATXAB) U6.H2(VSST) U6.H12(DGND) U6.H19(VSSATXAB) U6.H20(VSSATXAB) U6.J2(VSST) U6.J6(DGND) U6.J7(DGND) U6.J8(DGND) U6.J9(DGND) U6.J10(DGND) U6.J11(DGND) U6.J16(VSSCLK) U6.J17(VSSCLK) U6.J18(VSSCLK) U6.J19(VSSCLK) U6.J20(VSSCLK) U6.K1(VSST) U6.K3(VSST) U6.K4(VSST) U6.K20(VSSCLK) U6.L1(VSST) U6.L3(VSST) U6.L4(VSST) U6.L16(VSSCLK) U6.L20(VSSCLK) U6.M2(VSST) U6.M6(DGND) U6.M7(DGND) U6.M8(DGND) U6.M9(DGND) U6.M10(DGND) U6.M11(DGND) U6.M16(VSSCLK) U6.M18(VSSCLK) U6.M19(VSSCLK) U6.M20(VSSCLK) U6.N2(VSST) U6.N12(DGND) U6.N19(VSSATXCD) U6.N20(VSSATXCD) U6.P1(VSST) U6.P2(VSST) U6.P12(DGND) U6.P19(VSSATXCD) U6.R2(VSST) U6.R12(DGND) U6.R13(DGND) U6.R16(VSSATXCD) U6.R17(VSSATXCD) U6.R18(VSSATXCD) U6.R19(VSSATXCD) U6.T2(VSST) U6.T19(VSSATXCD) U6.T20(VSSATXCD) U6.U1(VSST) U6.U2(VSST) U6.U19(VSSATXCD) U6.U20(VSSATXCD) U6.V2(VSST) U6.V19(VSSATXCD) U6.W2(VSST) U6.W3(VSST) U6.W4(VSST) U6.W5(RXAGND) U6.W6(RXAGND) U6.W7(RXAGND) U6.W8(RXAGND) U6.W9(RXAGND) U6.W10(RXAGND) U6.W11(RXAGND) U6.W12(RXAGND) U6.W13(RXAGND) U6.W14(RXAGND) U6.W15(RXAGND) U6.W16(RXAGND) U6.W17(RXAGND) U6.W18(RXAGND) U6.W19(VSSATXCD) U6.Y1(VSST) U6.Y4(VSST) U6.Y5(RXAGND) U6.Y6(RXAGND) U6.Y9(RXAGND) U6.Y12(RXAGND) U6.Y15(RXAGND) U6.Y18(RXAGND) U6.Y19(VSSATXCD) U6.Y20(VSSATXCD)

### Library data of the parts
U6 = CMP-0084351-1: as U6 on sheet AFE2-POWER

## Sheet 00-CoverSheet.SchDoc
size 431 x 279 mm; Date: Not shown in title block; ApprovedBy: Not shown in title block; CheckedBy: Not shown in title block; Author: Not shown in title block; CompanyName: Not shown in title block; DrawnBy: Avinash N; Engineer: Not shown in title block; Organization: Not shown in title block; Address1: Not shown in title block; Address2: Not shown in title block; Address3: Not shown in title block; Address4: Not shown in title block; DocumentNumber: 1; Revision: Use project parameter SCH_Rev; SheetNumber: 1; SheetTotal: 32; PageSetup: Record=PageOptions¦CenterHorizontal=True¦CenterVertical=True¦PrintScale=1.00¦XCorrection=1.00¦YCorrection=1.00¦PrintKind=0¦BorderSize=5000000¦LeftOffset=0¦BottomOffset=0¦Orientation=2¦PaperLength=1000¦PaperWidth=1000¦Scale=100¦PaperSource=15¦PrintQuality=600¦MediaType=1¦DitherType=10¦PaperKind=Letter¦PrintScaleMode=1
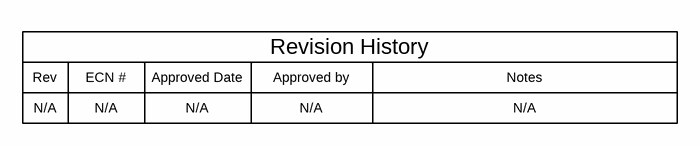
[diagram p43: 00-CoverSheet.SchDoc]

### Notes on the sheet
- Rev
- N/A
- ECN #
- Approved Date
- Approved by
- Revision History
- Notes

## Sheet EVM_Hardware.SchDoc
size 431 x 279 mm; Date: Not shown in title block; ApprovedBy: Not shown in title block; CheckedBy: Not shown in title block; Author: Not shown in title block; CompanyName: Not shown in title block; DrawnBy: Avinash N; Engineer: Not shown in title block; Organization: Not shown in title block; Address1: Not shown in title block; Address2: Not shown in title block; Address3: Not shown in title block; Address4: Not shown in title block; DocumentNumber: 1; Revision: Use project parameter SCH_Rev; SheetNumber: 32; SheetTotal: 32; PageSetup: Record=PageOptions¦CenterHorizontal=True¦CenterVertical=True¦PrintScale=1.00¦XCorrection=1.00¦YCorrection=1.00¦PrintKind=0¦BorderSize=5000000¦LeftOffset=0¦BottomOffset=0¦Orientation=2¦PaperLength=1000¦PaperWidth=1000¦Scale=100¦PaperSource=15¦PrintQuality=600¦MediaType=1¦DitherType=10¦PaperKind=Letter¦PrintScaleMode=1
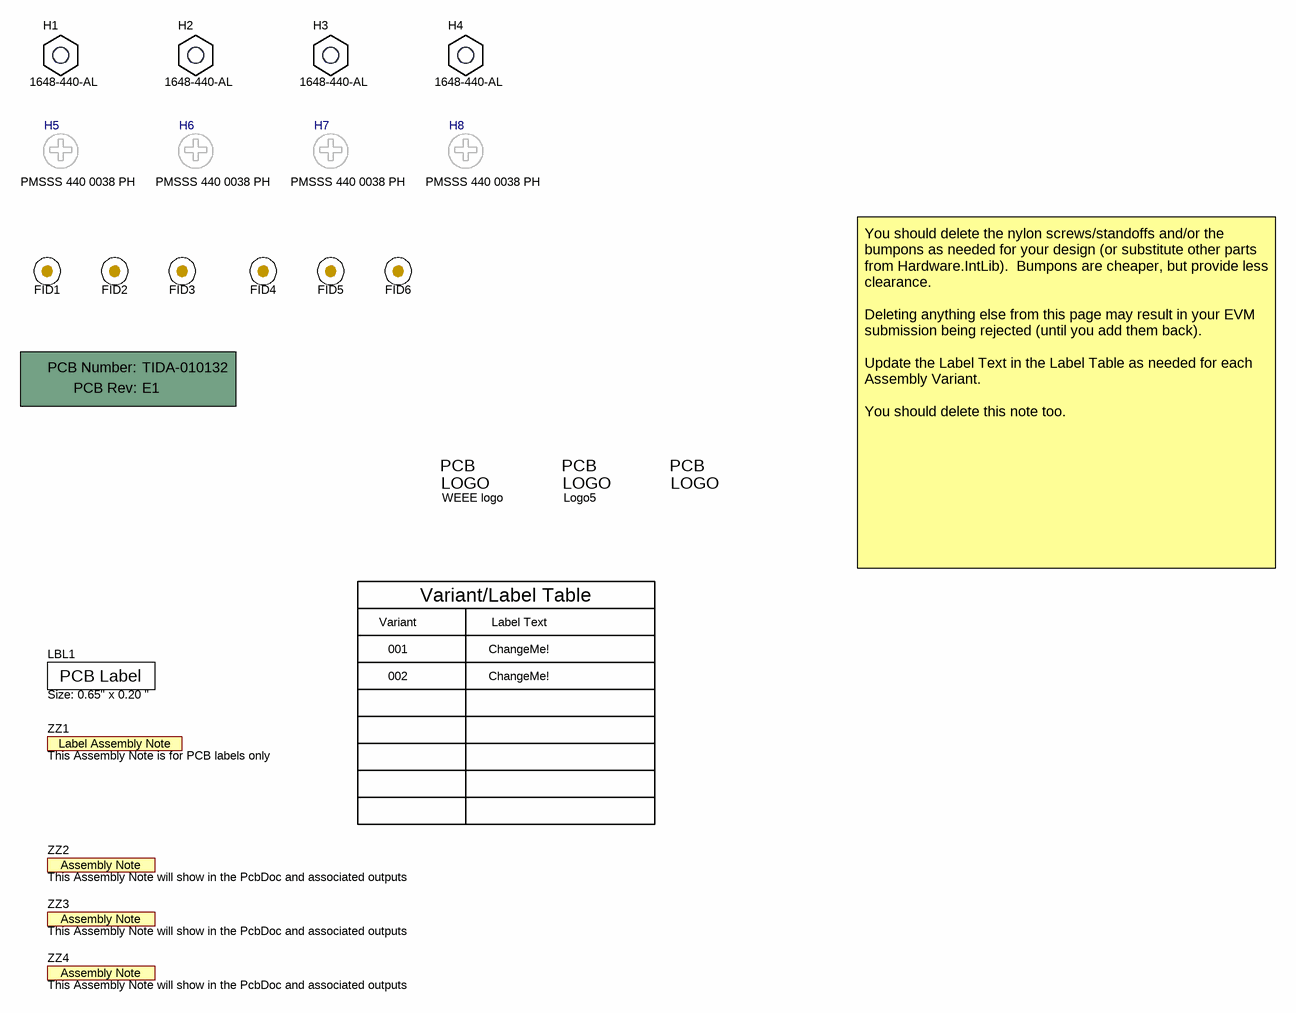
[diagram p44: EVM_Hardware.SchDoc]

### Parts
!PCB1  Printed Circuit Board  (value not drawn)  (mechanical)
FID1  Fiducial  [Fiducial10-20]  (value not drawn)
FID2  Fiducial  [Fiducial10-20]  (value not drawn)
FID3  Fiducial  [Fiducial10-20]  (value not drawn)
FID4  Fiducial  [Fiducial10-20]  (value not drawn)
FID5  Fiducial  [Fiducial10-20]  (value not drawn)
FID6  Fiducial  [Fiducial10-20]  (value not drawn)
H1  1648-440-AL  [TCBS-6-01]
H2  1648-440-AL  [TCBS-6-01]
H3  1648-440-AL  [TCBS-6-01]
H4  1648-440-AL  [TCBS-6-01]
H5  PMSSS 440 0038 PH  [BuildingFastener_MPMS_003_0005_PH]  (mechanical)
H6  PMSSS 440 0038 PH  [BuildingFastener_MPMS_003_0005_PH]  (mechanical)
H7  PMSSS 440 0038 PH  [BuildingFastener_MPMS_003_0005_PH]  (mechanical)
H8  PMSSS 440 0038 PH  [BuildingFastener_MPMS_003_0005_PH]  (mechanical)
LBL1  Size: 0.65" x 0.20 "  [Label_650x200]
Logo3  FCC disclaimer  [FCC_disclaimer]  (value not drawn)  (no BOM)
Logo4  WEEE logo  [WEEE_Minimum]  (no BOM)
Logo5  ESD Susceptible  [ESD_Overlay_small]  (value not drawn)  (no BOM)
ZZ1  This Assembly Note is for PCB labels only  [AssemblyNoteLabel]  (no BOM)
ZZ2  This Assembly Note will show in the PcbDoc and associated outputs  [AssemblyNote]  (no BOM)
ZZ3  This Assembly Note will show in the PcbDoc and associated outputs  [AssemblyNote]  (no BOM)
ZZ4  This Assembly Note will show in the PcbDoc and associated outputs  [AssemblyNote]  (no BOM)

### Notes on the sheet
- Variant
- Variant/Label Table
- Label Text
- You should delete the nylon screws/standoffs and/or the bumpons as needed for your design (or substitute other parts from Hardware.IntLib).  Bumpons are cheaper, but provide less clearance.
  Deleting anything else from this page may result in your EVM submission being rejected (until you add them back).
  Update the Label Text in the Label Table as needed for each Assembly Variant.
  You should delete this note too.
- 001
- 002
- ChangeMe!

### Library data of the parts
!PCB1 = PCB: Manufacturer: Any; PartNumber: TIDA-010132; SymbolCreator: a0412235
FID1-FID6 = Fiducial: Fiducial mark.  There is nothing to buy or mount.; SymbolCreator: codlsc
H1-H4 = TCBS-6-01: 3/16 RD X 1-3/16 LENGTH; Manufacturer: RAF Electronic Hardware; CompType: Standoff; SymbolCreator: a0412235
H5-H8 = MPMS 003 0005 PH: MACHINE SCREW PAN PHILLIPS 4-40; Manufacturer: B&F Fastener Supply; CompType: Hardware
LBL1 = THT-14-423-10: Thermal Transfer Printable Labels, 0.650" W x 0.200" H - 10,000 per roll; Manufacturer: Brady; SymbolCreator: a0412235; CompType: Label; Green_Lifecycle: Not Set; Green_REACh: Incomplete
Logo3 = FCC_disclaimer: SymbolCreator: a0412235
Logo4 = CMP-0074769-1
Logo5 = ESD_Susceptible: ESD Susceptible Symbol; SymbolCreator: a0412235
ZZ1 = AssemblyNoteLabel: SymbolCreator: a0412235
ZZ2-ZZ4 = AssemblyNote: SymbolCreator: codlsc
